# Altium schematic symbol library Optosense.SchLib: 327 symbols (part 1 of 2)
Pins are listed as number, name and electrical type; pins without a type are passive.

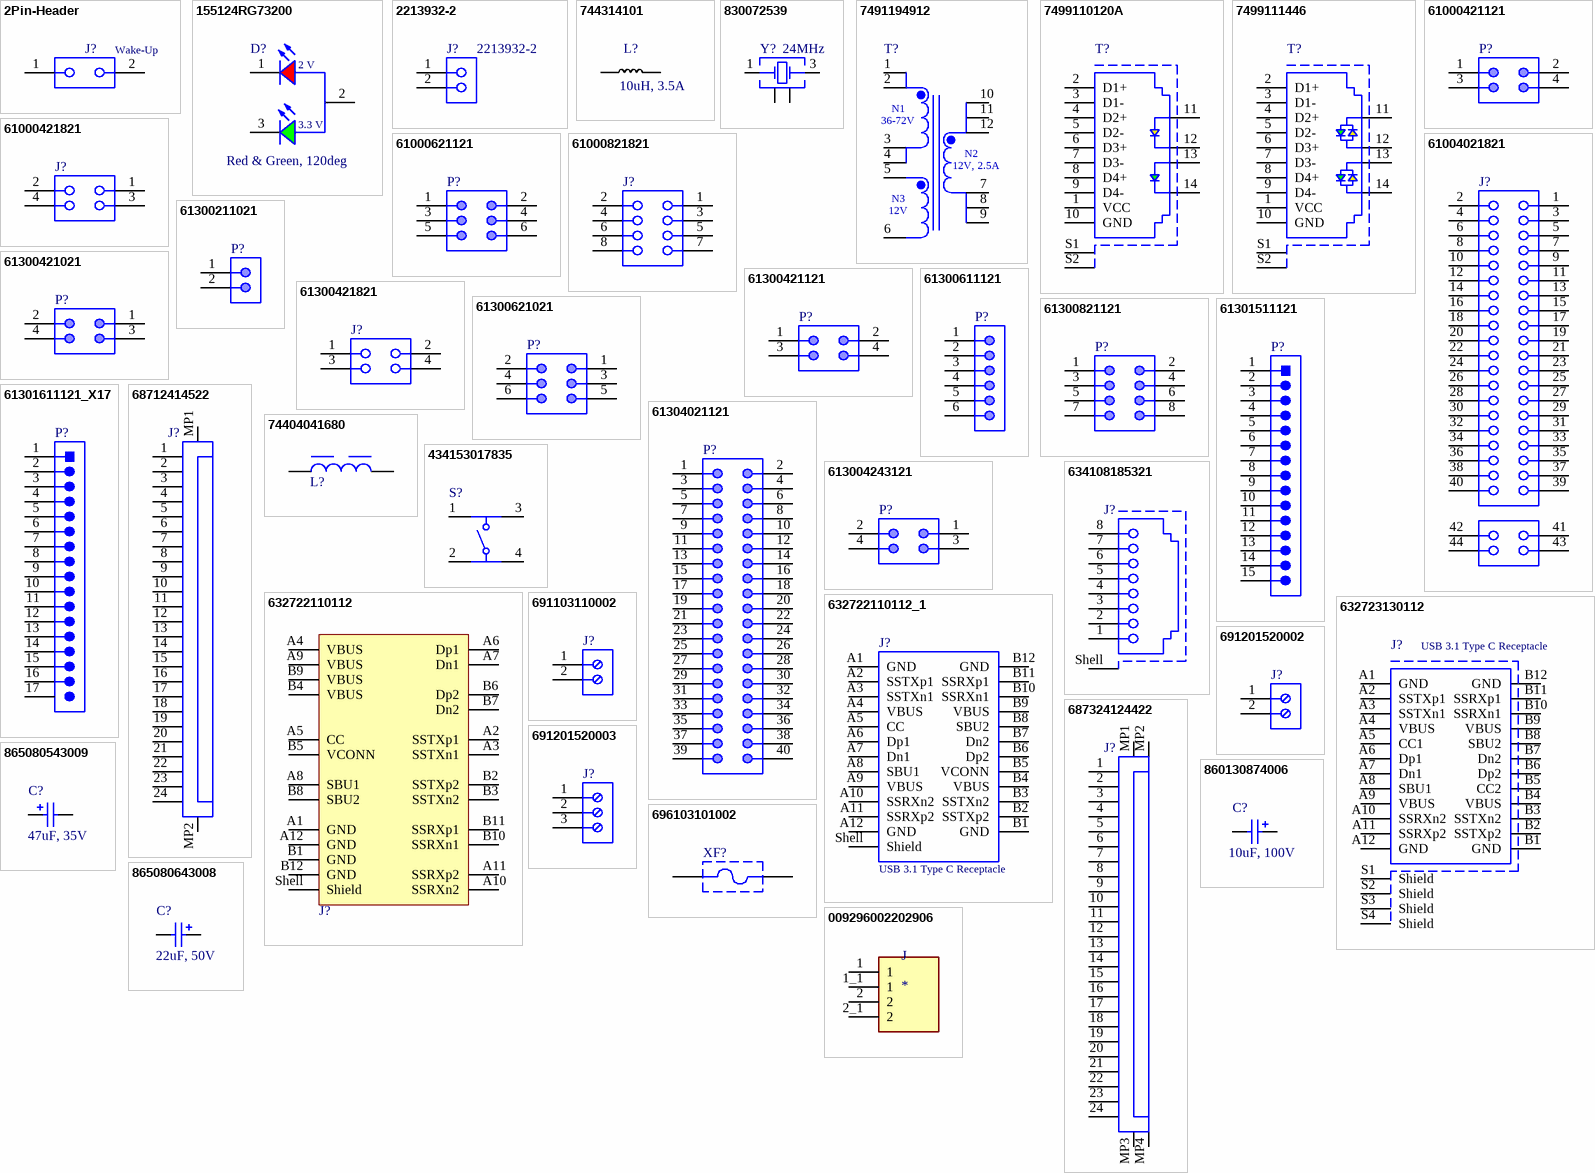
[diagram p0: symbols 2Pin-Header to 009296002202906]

## 2Pin-Header
designator J?, comment Wake-Up
2_Pin-Head_2.54mm
footprint SAMTEC-TSM-102-01-X-SV
pins: 1, 2

## 155124RG73200
designator D?, comment Red & Green, 120deg
WL-SBSW SMT Bi-color Side View Waterclear, size 1204, Red & Green, 120deg; Part Number: 155124RG73200; Luminous Intensity: 160mcd@Green, 60mcd@Red; Dominant Wavelength: 525nm@Green, 624nm@Red; Forward Voltage: 3.3V@Green, 2V@Red; Peak Wavelength: 520nm@Green, 632nm@Red; Chip Technology: AlInGaP + InGaN
footprint WL-SBSW_1204
pins: 1 K, 2 A, 3 K

## 2213932-2
designator J?
SMT TB R/A HEADER, 3.5MM, 2 POS
footprint 2213932-2
pins: 1, 2

## 744314101
designator L?, comment 10uH, 3.5A
WE-HCI SMT Flat Wire High Current Inductor, size 7050, 10uH, 3.5A; Manufacturer Part Number: 744314101; Manufacturer: Wurth Elektronik; DC Resistance: 33mOhm; Material: Superflux; Self Resonant Frequency: 40MHz; Saturation Current: 4A; Rated Inductance: 7.5uH
footprint WE-HCI_7050
pins: 1 (power), 2 (power)

## 830072539
designator Y?, comment 24MHz
WE-XTAL Quartz Crystal, SMT, IQXC-26, 24MHz, +/-15ppm; Manufacturer Part Number: 830072539; Manufacturer: Wurth Elektronik; Load Capacitance: 8pF
footprint WE-XTAL_IQXC-26 (Quartz Crystal, size IQXC-26, body 1.6x1.2mm)
pins: 1 Crystal, 2 GND & Lid, 3 Crystal, 4 GND & Lid

## 7491194912
designator T?
WE-PoE+ Power over Ethernet Plus Transformer, EFD20, 36-72Vin, 12Vout, 30W; Manufacturer Part Number: 7491194912; Manufacturer: Wurth Elektronik; Leakage Inductance: 0.545uH; Insulation Test Voltage: 1500VAC; Inductance: 42uH; Output Current: 2.5A; Output Voltage: 12V; Turns Ratio: 3:1:1; Input Voltage: 36-72V; Saturation Current: 6.6A; Switching Frequency: 250-400kHz
footprint WE-PoE+_EFD20
pins: 1, 2, 3, 4, 5, 6, 7, 8, 9, 10, 11, 12

## 7499110120A
designator T?
WE-RJ45 LAN Transformer, THT, 10/100/1000 Base-T, Port 1x1, Tab Vertical; Manufacturer Part Number: 7499110120A; Manufacturer: Wurth Elektronik; PoE: non-PoE; LED: yellow-green; USB: No
footprint 7499110120A (LAN Transformer, body 21.84x15.95mm)
pins: 1 VCC, 2 D1+, 3 D1-, 4 D2+, 5 D2-, 6 D3+, 7 D3-, 8 D4+, 9 D4-, 10 GND, 11, 12, 13, 14, S1 Shield, S2 Shield

## 7499111446
designator T?
WE-RJ45 LAN Transformer, THT, 10/100/1000 Base-T, Port 1x1, Tab Down; Manufacturer Part Number: 7499111446; Manufacturer: Wurth Elektronik; PoE: non-PoE; LED: green/yellow-green/yellow; USB: No; Shield Tabs: Yes
footprint 7499111446
pins: 1 VCC, 2 D1+, 3 D1-, 4 D2+, 5 D2-, 6 D3+, 7 D3-, 8 D4+, 9 D4-, 10 GND, 11, 12, 13, 14, S1 Shield, S2 Shield

## 61000421121
designator P?
WR-PHD Pin Header, SMT, pitch 2.54mm, Dual Row, Vertical, 4p; Manufacturer Part Number: 61000421121; Manufacturer: Wurth Elektronik; Pin Number: 4; Rated Current: 3A; Working Voltage: 250VAC; Withstanding Voltage: 500VAC; Contact Resistance: 20mOhm
footprint 61000421121 (Pin Header, pitch 2.54 mm, SMD, Vertical, dual row, 4p)
pins: 1, 2, 3, 4

## 61000421821
designator J?
WR-PHD Socket Header, SMT, pitch 2.54mm, Dual Row, Vertical, 4p; Manufacturer Part Number: 61000421821; Manufacturer: Wurth Elektronik; Pin Number: 4; Rated Current: 3A; Working Voltage: 250VAC; Withstanding Voltage: 600VAC; Contact Resistance: 20mOhm
footprint 61000421821
pins: 1, 2, 3, 4

## 61000621121
designator P?
WR-PHD Pin Header, SMT, pitch 2.54mm, Dual Row, Vertical, 6p; Manufacturer Part Number: 61000621121; Manufacturer: Wurth Elektronik; Pin Number: 6; Rated Current: 3A; Working Voltage: 250VAC; Withstanding Voltage: 500VAC; Contact Resistance: 20mOhm
footprint 61000621121
pins: 1, 2, 3, 4, 5, 6

## 61000821821
designator J?
WR-PHD Socket Header, SMT, pitch 2.54mm, Dual Row, Vertical, 8p; Manufacturer Part Number: 61000821821; Manufacturer: Wurth Elektronik; Pin Number: 8; Rated Current: 3A; Working Voltage: 250VAC; Withstanding Voltage: 600VAC; Contact Resistance: 20mOhm
footprint 61000821821
pins: 1, 2, 3, 4, 5, 6, 7, 8

## 61004021821
designator J?
WR-PHD Socket Header, SMT, pitch 2.54mm, Dual Row, Vertical, 40pin; Part Number: 61004021821; Pin Number: 40; Gender: Female; Rated Current: 3A; Working Voltage: 250VAC; Withstanding Voltage: 600VAC; Contact Resistance: 20mOhm
footprint 61004021821
pins: 1, 2, 3, 4, 5, 6, 7, 8, 9, 10, 11, 12, 13, 14, 15, 16, 17, 18, 19, 20, 21, 22, 23, 24, 25, 26, 27, 28, 29, 30, 31, 32, 33, 34, 35, 36, 37, 38, 39, 40, 41, 42, 43, 44

## 61300211021
designator P?
WR-PHD Pin Header, THT, pitch 2.54mm, Single Row, Angled, 2p; Manufacturer Part Number: 61300211021; Manufacturer: Wurth Elektronik; Pin Number: 2; Rated Current: 3A; Working Voltage: 250VAC; Withstanding Voltage: 500VAC; Contact Resistance: 20mOhm
footprint 61300211021
pins: 1, 2

## 61300421021
designator P?
WR-PHD Pin Header, THT, pitch 2.54mm, Dual Row, Angled, 4p; Manufacturer Part Number: 61300421021; Manufacturer: Wurth Elektronik; Pin Number: 4; Rated Current: 3A; Working Voltage: 250VAC; Withstanding Voltage: 500VAC; Contact Resistance: 20mOhm
footprint 61300421021 (Pin Header, pitch 2.54 mm, THT, Angled, dual row, 4p)
pins: 1, 2, 3, 4

## 61300421121
designator P?
WR-PHD Pin Header, THT, pitch 2.54mm, Dual Row, Vertical, 4p; Manufacturer Part Number: 61300421121; Manufacturer: Wurth Elektronik; Pin Number: 4; Rated Current: 3A; Working Voltage: 250VAC; Withstanding Voltage: 500VAC; Contact Resistance: 20mOhm
footprint 61300421121
pins: 1, 2, 3, 4

## 61300421821
designator J?
WR-PHD Socket Header, THT, pitch 2.54mm, Dual Row, Vertical, 4p; Manufacturer Part Number: 61300421821; Manufacturer: Wurth Elektronik; Pin Number: 4; Rated Current: 3A; Working Voltage: 250VAC; Withstanding Voltage: 500VAC; Contact Resistance: 20mOhm
footprint 61300421821 (Socket Header, Pitch 2.54 mm, THT, Vertical, dual row, 4p)
pins: 1, 2, 3, 4

## 61300611121
designator P?
WR-PHD Pin Header, THT, pitch 2.54mm, Single Row, Vertical, 6p; Manufacturer Part Number: 61300611121; Manufacturer: Wurth Elektronik; Pin Number: 6; Rated Current: 3A; Working Voltage: 250VAC; Withstanding Voltage: 500VAC; Contact Resistance: 20mOhm
footprint 61300611121
pins: 1, 2, 3, 4, 5, 6

## 61300621021
designator P?
WR-PHD Pin Header, THT, pitch 2.54mm, Dual Row, Angled, 6p; Manufacturer Part Number: 61300621021; Manufacturer: Wurth Elektronik; Pin Number: 6; Rated Current: 3A; Working Voltage: 250VAC; Withstanding Voltage: 500VAC; Contact Resistance: 20mOhm
footprint 61300621021
pins: 1, 2, 3, 4, 5, 6

## 61300821121
designator P?
WR-PHD Pin Header, THT, pitch 2.54mm, Dual Row, Vertical, 8p; Manufacturer Part Number: 61300821121; Manufacturer: Wurth Elektronik; Pin Number: 8; Rated Current: 3A; Working Voltage: 250VAC; Withstanding Voltage: 500VAC; Contact Resistance: 20mOhm
footprint 61300821121
pins: 1, 2, 3, 4, 5, 6, 7, 8

## 61301511121
designator P?
WR-PHD Pin Header, THT, pitch 2.54mm, Single Row, Vertical, 15p; Manufacturer Part Number: 61301511121; Manufacturer: Wurth Elektronik; Pin Number: 15; Rated Current: 3A; Working Voltage: 250VAC; Withstanding Voltage: 500VAC; Contact Resistance: 20mOhm
footprint 61301511121
pins: 1, 2, 3, 4, 5, 6, 7, 8, 9, 10, 11, 12, 13, 14, 15

## 61301611121_X17
designator P?
WR-PHD Pin Header, THT, pitch 2.54mm, Single Row, Vertical, 16p; Manufacturer Part Number: 61301611121; Manufacturer: Wurth Elektronik; Pin Number: 16; Rated Current: 3A; Working Voltage: 250VAC; Withstanding Voltage: 500VAC; Contact Resistance: 20mOhm
footprint 61301611121_X17 (Pin Header, pitch 2.54 mm, THT, Vertical, single row, 16p)
pins: 1, 2, 3, 4, 5, 6, 7, 8, 9, 10, 11, 12, 13, 14, 15, 16, 17

## 61304021121
designator P?
WR-PHD Pin Header, THT, pitch 2.54mm, Dual Row, Vertical, 40p; Manufacturer Part Number: 61304021121; Manufacturer: Wurth Elektronik; Pin Number: 40; Rated Current: 3A; Working Voltage: 250VAC; Withstanding Voltage: 500VAC; Contact Resistance: 20mOhm
footprint 61304021121
pins: 1, 2, 3, 4, 5, 6, 7, 8, 9, 10, 11, 12, 13, 14, 15, 16, 17, 18, 19, 20, 21, 22, 23, 24, 25, 26, 27, 28, 29, 30, 31, 32, 33, 34, 35, 36, 37, 38, 39, 40

## 68712414522
designator J?
WR-FPC SMT ZIF Horizontal Bottom Contact, pitch 0.5mm, 24p; Part Number: 68712414522; Contact Resistance: 20mOhm; Pin Number: 24; Working Voltage: 50VAC; Rated Current: 0.5A
footprint 68712414522
pins: 1, 2, 3, 4, 5, 6, 7, 8, 9, 10, 11, 12, 13, 14, 15, 16, 17, 18, 19, 20, 21, 22, 23, 24, MP1, MP2

## 74404041680
designator L?, comment 68µH, 0.45A  (value not drawn)
WE-LQS SMT Power Inductor, size 4012, 68µH, 0.45A, 1.495Ω; Manufacturer Part Number: 74404041680; Manufacturer: Wurth Elektronik; Case/Size Code: 4012; Saturation Current: 0.48A; Self Resonant Frequency: 13MHz
footprint WE-LQS_4012 (SMD Power Inductor, 2-Leads, body 4x4mm)
pins: 1, 2

## 434153017835
designator S?
WS-TASV J-Bend SMT Tact Switch, 3.5x2.9x1.7mm, 350gf; Manufacturer Part Number: 434153017835; Manufacturer: Wurth Elektronik; Rated Voltage: 12VDC; Rated Current: 50mA; Washable: No
footprint 434153017835 (Tact Switch, SMD, body 3.5x2.9mm)
pins: 1, 2, 3, 4

## 613004243121
designator P?
WR-PHD Pin Header, THT, pitch 2.54mm, Dual Row, Angled, 4p; Manufacturer Part Number: 61300421021; Manufacturer: Wurth Elektronik; Pin Number: 4; Rated Current: 3A; Working Voltage: 250VAC; Withstanding Voltage: 500VAC; Contact Resistance: 20mOhm
footprint 613004243121
pins: 1, 2, 3, 4

## 632722110112
designator J?  (value not drawn)
WR-USB 3.1 Type C, Receptacle, Vertical, SMT; Manufacturer: Wurth Elektronik; Interface Type: Type C; Number of Ports: 1; Rated Current: 5A; Working Voltage: 20VAC
footprint 632722110112
pins: A1 GND, A2 SSTXp1, A3 SSTXn1, A4 VBUS, A5 CC, A6 Dp1, A7 Dn1, A8 SBU1, A9 VBUS, A10 SSRXn2, A11 SSRXp2, A12 GND, B1 GND, B2 SSTXp2, B3 SSTXn2, B4 VBUS, B5 VCONN, B6 Dp2, B7 Dn2, B8 SBU2, B9 VBUS, B10 SSRXn1, B11 SSRXp1, B12 GND, Shell Shield

## 632722110112_1
designator J?, comment USB 3.1 Type C Receptacle
USB 3.1 Type C, Receptacle, Vertical, SMT; Manufacturer: Wurth Elektronik; Manufacturer Part Number: 632722110112; Rated Current: 5A; Pin Number: 24; Interface Type: Type C; Working Voltage: 20VAC
footprint 632722110112 (USB_Type C 3.1_Vertical_SMT_1,0mm)
pins: A1 GND, A2 SSTXp1, A3 SSTXn1, A4 VBUS, A5 CC, A6 Dp1, A7 Dn1, A8 SBU1, A9 VBUS, A10 SSRXn2, A11 SSRXp2, A12 GND, B1 GND, B2 SSTXp2, B3 SSTXn2, B4 VBUS, B5 VCONN, B6 Dp2, B7 Dn2, B8 SBU2, B9 VBUS, B10 SSRXn1, B11 SSRXp1, B12 GND, Shell Shield

## 632723130112
designator J?, comment USB 3.1 Type C Receptacle
USB 3.1 Type C, Receptacle, Horizontal, THR; Part Number: 632723130112; Rated Current: 5A; Pin Number: 24; Interface Type: Type C; Working Voltage: 20VAC
footprint 632723130112
pins: A1 GND, A2 SSTXp1, A3 SSTXn1, A4 VBUS, A5 CC1, A6 Dp1, A7 Dn1, A8 SBU1, A9 VBUS, A10 SSRXn2, A11 SSRXp2, A12 GND, B1 GND, B2 SSTXp2, B3 SSTXn2, B4 VBUS, B5 CC2, B6 Dp2, B7 Dn2, B8 SBU2, B9 VBUS, B10 SSRXn1, B11 SSRXp1, B12 GND, S1 Shield, S2 Shield, S3 Shield, S4 Shield

## 634108185321
designator J?
WR-MJ Modular Jack SMT Vertical Shielded with Solder Tab 8P8C Top Entry; Manufacturer: Wurth Elektronik; Manufacturer Part Number: 634108185321; Rated Current: 1.5A; Contact Resistance: 30mOhm; Insulation Resistance: 1000MOhm; Working Voltage: 125VAC; Withstanding Voltage: 1000VAC; LED: No; Port Number: 1; Shielded: Yes
footprint 634108185321 (Modular Jack Vertical Shielded SMT  with Solder Tab 8P8C Top Entry)
pins: 1, 2, 3, 4, 5, 6, 7, 8, Shell

## 687324124422
designator J?
WR-FPC SMT ZIF Vertical, pitch 0.5mm, 24p; Part Number: 687324124422; Contact Resistance: 20mOhm; Pin Number: 24; Working Voltage: 50VAC; Rated Current: 0.5A
footprint 687324124422
pins: 1, 2, 3, 4, 5, 6, 7, 8, 9, 10, 11, 12, 13, 14, 15, 16, 17, 18, 19, 20, 21, 22, 23, 24, MP1, MP2, MP3, MP4

## 691103110002
designator J?
WR-TBL Serie 1031 Horizontal Entry Modular, Pressure Clamp, THT, pitch 3.5mm, 2p; Manufacturer Part Number: 691103110002; Manufacturer: Wurth Elektronik; Modularity: Yes; PCB/Cable/Panel: PCB; Pin Number: 2; Rated Current [UL]: 10A; Working Voltage [UL]: 125VAC
footprint 691103110002 (3,50mm - modular - blue - Horizontal wire entry - Pressure clamp - 8,4mm height - 02p)
pins: 1, 2

## 691201520002
designator J?
WR-TBL Serie 2015 45deg Entry Modular, Rising Cage Clamp, pitch 5.08mm, 2p; Part Number: 691201520002; Compliance: ROHS & Reach; Modularity: Yes; PCB/Cable/Panel: PCB; Pin Number: 2; Rated Current [UL]: 16A; Working Voltage [UL]: 300VAC
footprint 691201520002
pins: 1, 2

## 691201520003
designator J?
WR-TBL Serie 2015 45deg Entry Modular, Rising Cage Clamp, pitch 5.08mm, 3p; Part Number: 691201520003; Compliance: ROHS & Reach; Modularity: Yes; PCB/Cable/Panel: PCB; Pin Number: 3; Rated Current [UL]: 16A; Working Voltage [UL]: 300VAC
footprint 691201520003
pins: 1, 2, 3

## 696103101002
designator XF?
WR-FSH Fuseholder SMT Blocks PCB Clip Cover; Manufacturer Part Number: 696103101002; Manufacturer: Wurth Elektronik; Fuse Size: 5x20mm
footprint 696103101002
pins: 1, 2

## 860130874006
designator C?, comment 10uF, 100V
WCAP-ATET Aluminum Electrolytic Capacitor, Radial, THT, D8xH11.5mm, 10uF, 100V; Manufacturer Part Number: 860130874006; Manufacturer: Wurth Elektronik; Dissipation Factor: 7%; Endurance: 1000h; Leakage Current: 10uA; Ripple Current: 60mA; Capacitance Tolerance: +/-20%; Rated Voltage: 100VDC; Technical Reference: ATGE115100M100DSPA7A000
footprint WCAP-ATET_8x11.5
pins: 1 N, 2 P

## 865080543009
designator C?, comment 47uF, 35V
WCAP-ASLI Aluminum Electrolytic Capacitor, V-Chip, SMT, D6.3xH5.5mm, 47uF, 35V; Manufacturer Part Number: 865080543009; Manufacturer: Wurth Elektronik; Technical Reference: ASED055470M035DVCTBB000; Ripple Current: 240mA; Capacitance Tolerance: +/-20%; Leakage Current: 16.45uA; Endurance: 2000h; Dissipation Factor: 14%; Rated Voltage: 35VDC
footprint WCAP-ASLI_D6.3H5.5
pins: 1 P, 2 N

## 865080643008
designator C?, comment 22uF, 50V
WCAP-ASLI Aluminum Electrolytic Capacitor, V-Chip, SMT, D6.3xH5.5mm, 22uF, 50V; Manufacturer Part Number: 865080643008; Manufacturer: Wurth Elektronik; Dissipation Factor: 12%; Endurance: 2000h; Leakage Current: 11uA; Ripple Current: 150mA; Capacitance Tolerance: +/-20%; Rated Voltage: 50VDC; Technical Reference: ASED055220M050DVCTBB000
footprint WCAP-ASLI_6.3x5.5
pins: 1 N, 2 P

## 009296002202906
designator J
2 Position Individual Wires Connector White Poke-In 20-26 AWG Surface Mount, Right Angle; MF: AVX; MP: 009296002202906
footprint AVX_009296002202906
pins: 1, 1_1 1, 2, 2_1 2

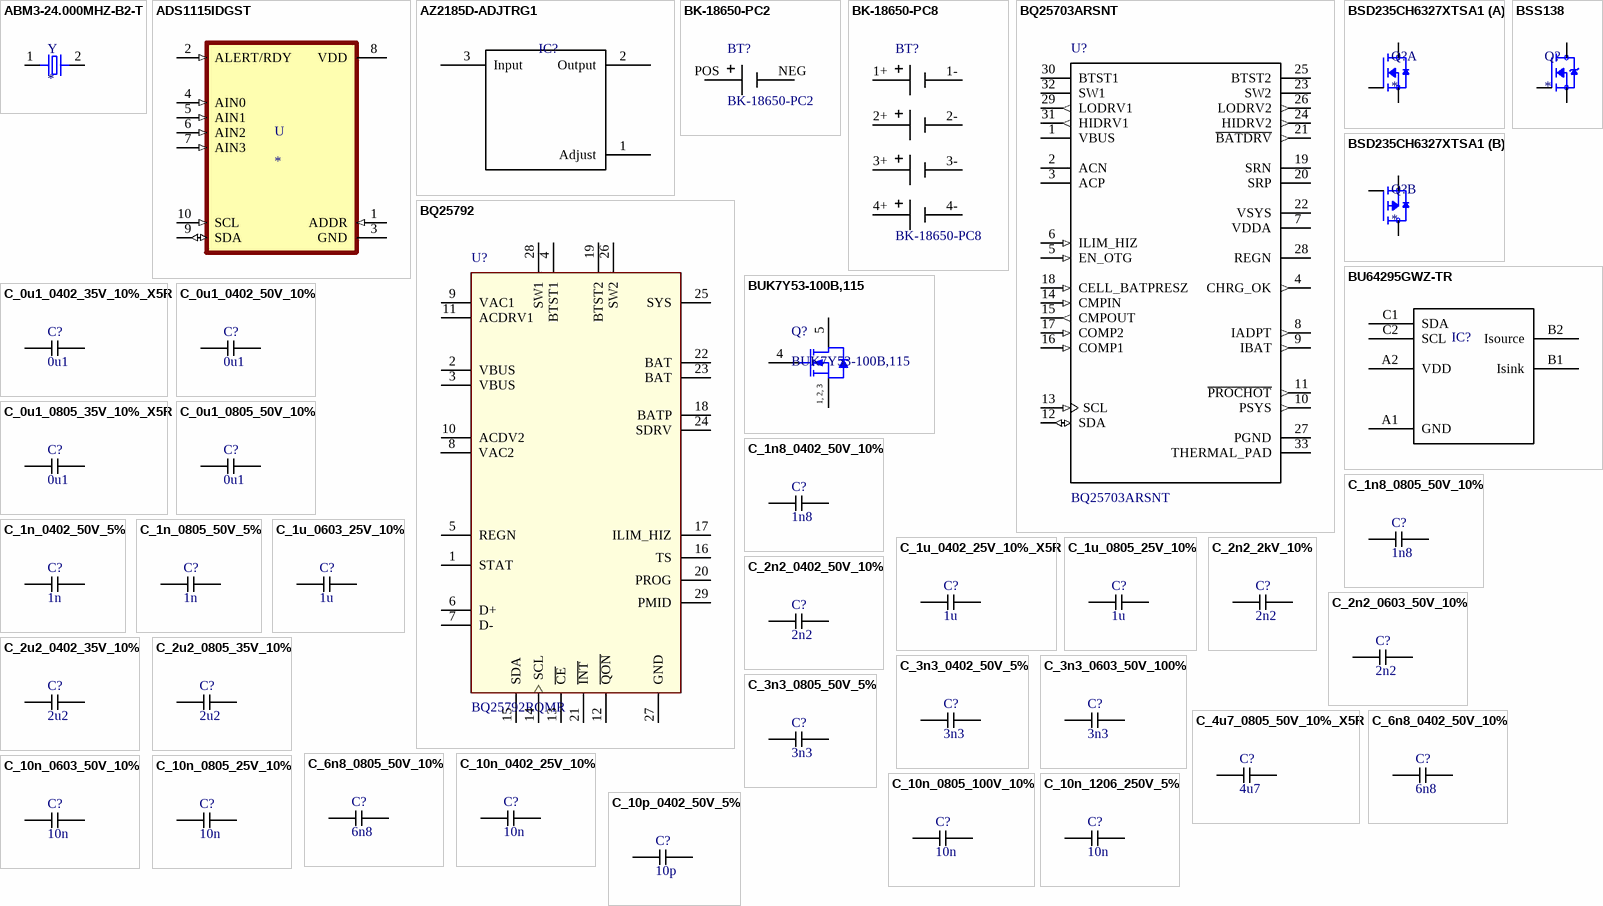
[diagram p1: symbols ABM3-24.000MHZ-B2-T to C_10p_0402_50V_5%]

## ABM3-24.000MHZ-B2-T
designator Y
24MHz Â±20ppm Crystal 18pF 30 Ohms 2-SMD, No Lead; MP: ABM3-24.000MHZ-B2-T; MF: Abracon
footprint XTAL500X320X130N
pins: 1, 2

## ADS1115IDGST
designator U
16-Bit 860SPS 4-Ch Delta-Sigma ADC With PGA, Oscillator, Vref, Comparator, and I2C; MP: ADS1115IDGST; MF: Texas Instruments
footprint SOP50P490X110-10N
pins: 1 ADDR (in), 2 ALERT/RDY (in), 3 GND (power), 4 AIN0 (in), 5 AIN1 (in), 6 AIN2 (in), 7 AIN3 (in), 8 VDD (power), 9 SDA (io), 10 SCL (in)

## AZ2185D-ADJTRG1
designator IC?
footprint DPAK229P990X239-3N
pins: 1 Adjust, 2 Output, 3 Input

## BK-18650-PC2
designator BT?
Battery Holder _Open_ 18650 1 Cell PC Pin; MF: MPD
footprint *BAT_BK-18650-PC2_BK-18650-PC2(Primary)
pins: NEG, POS

## BK-18650-PC8
designator BT?
Battery Holder _Open_ 18650 4 Cell PC Pin; MF: MPD
footprint *BAT_BK-18650-PC8_BK-18650-PC8(Primary)
pins: 1+, 1-, 2+, 2-, 3+, 3-, 4+, 4-

## BQ25703ARSNT
designator U?
Battery Battery Monitor IC Multi-Chemistry 32-WQFN _4x4_; MF: Texas Instruments
footprint *QFN40P400X400X80-33N
pins: 1 VBUS (power), 2 ACN (power), 3 ACP (power), 4 CHRG_OK (out), 5 EN_OTG (in), 6 ILIM_HIZ (in), 7 VDDA (power), 8 IADPT (out), 9 IBAT (out), 10 PSYS (out), 11 ~{PROCHOT} (out), 12 SDA (io), 13 SCL (in), 14 CMPIN (in), 15 CMPOUT (out), 16 COMP1 (in), 17 COMP2 (in), 18 CELL_BATPRESZ (in), 19 SRN (power), 20 SRP (power), 21 ~{BATDRV} (out), 22 VSYS (power), 23 SW2 (power), 24 HIDRV2 (out), 25 BTST2 (power), 26 LODRV2 (out), 27 PGND (power), 28 REGN (power), 29 LODRV1 (out), 30 BTST1 (power), 31 HIDRV1 (out), 32 SW1 (power), 33 THERMAL_PAD (power)

## BQ25792
designator U?, comment BQ25792RQMR
Battery Charger IC, QFN (29) _4x4_; MF: Texas Instruments
footprint Texas_Instruments_RQM0029A_MFG
pins: 1 STAT (power), 2 VBUS (power), 3 VBUS (power), 4 BTST1 (power), 5 REGN (power), 6 D+ (power), 7 D- (power), 8 VAC2 (power), 9 VAC1 (power), 10 ACDV2 (power), 11 ACDRV1 (power), 12 ~{QON} (power), 13 ~{CE} (power), 14 SCL, 15 SDA, 16 TS (power), 17 ILIM_HIZ (power), 18 BATP (power), 19 BTST2 (power), 20 PROG (power), 21 ~{INT} (power), 22 BAT (power), 23 BAT (power), 24 SDRV (power), 25 SYS (power), 26 SW2 (power), 27 GND (power), 28 SW1 (power), 29 PMID (power)

## BSD235CH6327XTSA1
designator Q?
footprint SOT363_INFINEON
part A pins: 1 S, 2 G2, 6 D
part B pins: 3 D, 4 S, 5 G1

## BSS138
designator Q?
N-Channel 50V 220mA (Ta) 360mW (Ta) Surface Mount SOT-23-3; MP: BSS138; MF: ON Semiconductor
footprint SOT95P240X111-3N
pins: 1 G, 2 S, 3 D

## BU64295GWZ-TR
designator IC?
footprint UCSP30L1-6
pins: A1 GND, A2 VDD, B1 Isink, B2 Isource, C1 SDA, C2 SCL

## BUK7Y53-100B,115
designator Q?
N-Channel TrenchMOS Standard Level FET, 100 V, 24.8 A, 5-Pin SOT669, Tape and Reel; Manufacturer: NXP Semiconductors; VGSth [typ] (V): 3; Packing: Tape & Reel; IDM [max] (A): 99; VDS [max] (V): 100; ID [max] (A): 24.8; Channel Type: N; Automotive Qualified: Y; Qr [typ] (nC): 155
footprint NXP-SOT669_M
footprint NXP-SOT669_N
footprint NXP-SOT669_L
pins: 1 S "source", 2 S "source", 3 S "source", 4 G "gate", 5 D "mounting base; connected to drain"

## C_0u1_0402_35V_10%_X5R
designator C?, comment 0u1
GMK105BJ104KV-F
footprint C_0402
pins: 1 (power), 2 (power)

## C_0u1_0402_50V_10%
designator C?, comment 0u1
GRM155R71H104KE14J
footprint C_0402
pins: 1 (power), 2 (power)

## C_0u1_0805_35V_10%_X5R
designator C?, comment 0u1
GMK212BJ104KGHT
footprint C_0805
pins: 1 (power), 2 (power)

## C_0u1_0805_50V_10%
designator C?, comment 0u1
885012207098
footprint C_0805
pins: 1 (power), 2 (power)

## C_1n8_0402_50V_10%
designator C?, comment 1n8
GCM155R71H182JA37D
footprint C_0402
pins: 1 (power), 2 (power)

## C_1n8_0805_50V_10%
designator C?, comment 1n8
CC0805KRX7R9BB182
footprint C_0805
pins: 1 (power), 2 (power)

## C_1n_0402_50V_5%
designator C?, comment 1n
04025C102JAT2A
footprint C_0402
pins: 1 (power), 2 (power)

## C_1n_0805_50V_5%
designator C?, comment 1n
C0805C102J5RAC
footprint C_0805
pins: 1 (power), 2 (power)

## C_1u_0402_25V_10%_X5R
designator C?, comment 1u
04023D105KAT2A
footprint C_0402
pins: 1 (power), 2 (power)

## C_1u_0603_25V_10%
designator C?, comment 1u
TMK107B7105KA-T
footprint C_0603
pins: 1 (power), 2 (power)

## C_1u_0805_25V_10%
designator C?, comment 1u
C0805C105K3RACAUTO
footprint C_0805
pins: 1 (power), 2 (power)

## C_2n2_2kV_10%
designator C?, comment 2n2
CK45-B3DD222KYVNA
footprint C_CK45
pins: 1 (power), 2 (power)

## C_2n2_0402_50V_10%
designator C?, comment 2n2
C0402C222K5RAC
footprint C_0402
pins: 1 (power), 2 (power)

## C_2n2_0603_50V_10%
designator C?, comment 2n2
06035C222KAT4A
footprint C_0603
pins: 1 (power), 2 (power)

## C_2u2_0402_35V_10%
designator C?, comment 2u2
GRM155R6YA225KE11D
footprint C_0402
pins: 1 (power), 2 (power)

## C_2u2_0805_35V_10%
designator C?, comment 2u2
C2012X5R1V225K085AB
footprint C_0805
pins: 1 (power), 2 (power)

## C_3n3_0402_50V_5%
designator C?, comment 3n3
CC0402JRX7R9BB332
footprint C_0402
pins: 1 (power), 2 (power)

## C_3n3_0603_50V_100%
designator C?, comment 3n3
VJ0603Y332KXACW1BC
footprint C_0603
pins: 1 (power), 2 (power)

## C_3n3_0805_50V_5%
designator C?, comment 3n3
CC0805JRX7R9BB332
footprint C_0805
pins: 1 (power), 2 (power)

## C_4u7_0805_50V_10%_X5R
designator C?, comment 4u7
GRM21BR61H475KE51L
footprint C_0805
pins: 1 (power), 2 (power)

## C_6n8_0402_50V_10%
designator C?, comment 6n8
AC0402KRX7R9BB682
footprint C_0402
pins: 1 (power), 2 (power)

## C_6n8_0805_50V_10%
designator C?, comment 6n8
885012207091
footprint C_0805
pins: 1 (power), 2 (power)

## C_10n_0402_25V_10%
designator C?, comment 10n
885012205050
footprint C_0402
pins: 1 (power), 2 (power)

## C_10n_0603_50V_10%
designator C?, comment 10n
C0603C103J5RACTU
footprint C_0603
pins: 1 (power), 2 (power)

## C_10n_0805_25V_10%
designator C?, comment 10n
885012207066
footprint C_0805
pins: 1 (power), 2 (power)

## C_10n_0805_100V_10%
designator C?, comment 10n
C0805C103K1RACTU
footprint C_0805
pins: 1 (power), 2 (power)

## C_10n_1206_250V_5%
designator C?, comment 10n
C1206C103JARACTU
footprint C_1206
pins: 1 (power), 2 (power)

## C_10p_0402_50V_5%
designator C?, comment 10p
885012005055
footprint C_0402
pins: 1 (power), 2 (power)

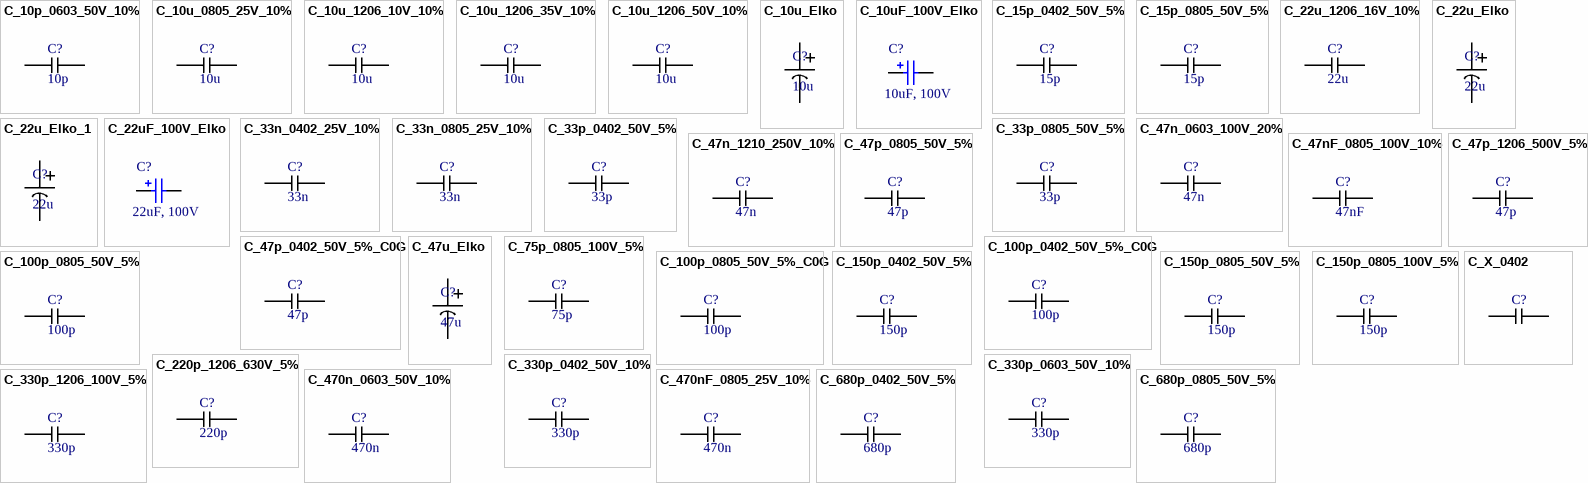
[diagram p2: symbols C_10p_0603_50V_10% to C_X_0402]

## C_10p_0603_50V_10%
designator C?, comment 10p
06035C100K4T4A
footprint C_0603
pins: 1 (power), 2 (power)

## C_10u_0805_25V_10%
designator C?, comment 10u
GRJ21BR61E106KE01K
footprint C_0805
pins: 1 (power), 2 (power)

## C_10u_1206_10V_10%
designator C?, comment 10u
LMK316B7106KL-T
footprint C_1206
pins: 1 (power), 2 (power)

## C_10u_1206_35V_10%
designator C?, comment 10u
GMK316BJ106KL-T
footprint C_1206
pins: 1 (power), 2 (power)

## C_10u_1206_50V_10%
designator C?, comment 10u
UMK316BBJ106KL-T
footprint C_1206
pins: 1 (power), 2 (power)

## C_10u_Elko
designator C?, comment 10u
ECA-2AHG100B
footprint Panasonic_ECA-2AHG220_0
pins: 1 - (power), 2 + (power)

## C_10uF_100V_Elko
designator C?, comment 10uF, 100V
EEE-2AA100P; Manufacturer Part Number: 865080543009; Manufacturer: Wurth Elektronik; Technical Reference: ASED055470M035DVCTBB000; Ripple Current: 240mA; Capacitance Tolerance: +/-20%; Leakage Current: 16.45uA; Endurance: 2000h; Dissipation Factor: 14%; Capacitance: 47uF; Rated Voltage: 35VDC
footprint CAPAE830X1080N
pins: 1 P, 2 N

## C_15p_0402_50V_5%
designator C?, comment 15p
885012005056
footprint C_0402
pins: 1 (power), 2 (power)

## C_15p_0805_50V_5%
designator C?, comment 15p
885012007052
footprint C_0805
pins: 1 (power), 2 (power)

## C_22u_1206_16V_10%
designator C?, comment 22u
EMK316ABJ226KL-T
footprint C_1206
pins: 1 (power), 2 (power)

## C_22u_Elko
designator C?, comment 22u
UKL2A220KPD
footprint C_10x12.5
pins: 1 - (power), 2 + (power)

## C_22u_Elko_1
designator C?, comment 22u
ECA-2AHG220B
footprint Panasonic_ECA-2AHG220_0
pins: 1 - (power), 2 + (power)

## C_22uF_100V_Elko
designator C?, comment 22uF, 100V
EEE-2AA220P; Manufacturer Part Number: 865080543009; Manufacturer: Wurth Elektronik; Technical Reference: ASED055470M035DVCTBB000; Ripple Current: 240mA; Capacitance Tolerance: +/-20%; Leakage Current: 16.45uA; Endurance: 2000h; Dissipation Factor: 14%; Capacitance: 47uF; Rated Voltage: 35VDC
footprint CAPAE830X1080N
pins: 1 P, 2 N

## C_33n_0402_25V_10%
designator C?, comment 33n
885012205053
footprint C_0402
pins: 1 (power), 2 (power)

## C_33n_0805_25V_10%
designator C?, comment 33n
885012207069
footprint C_0805
pins: 1 (power), 2 (power)

## C_33p_0402_50V_5%
designator C?, comment 33p
885012005058
footprint C_0402
pins: 1 (power), 2 (power)

## C_33p_0805_50V_5%
designator C?, comment 33p
C0805C330J5GACTU
footprint C_0805
pins: 1 (power), 2 (power)

## C_47n_0603_100V_20%
designator C?, comment 47n
C0603C473M1RACTU
footprint C_0603
pins: 1 (power), 2 (power)

## C_47n_1210_250V_10%
designator C?, comment 47n
QMK325B7473KN-T
footprint C_1210
pins: 1 (power), 2 (power)

## C_47nF_0805_100V_10%
designator C?, comment 47nF
X7R0805473K100DFCT10000
footprint C_0805
pins: 1 (power), 2 (power)

## C_47p_0402_50V_5%_C0G
designator C?, comment 47p
885012005059
footprint C_0402
pins: 1 (power), 2 (power)

## C_47p_0805_50V_5%
designator C?, comment 47p
C0805C470J5GACTU
footprint C_0805
pins: 1 (power), 2 (power)

## C_47p_1206_500V_5%
designator C?, comment 47p
1206N470J501CT
footprint C_1206
pins: 1 (power), 2 (power)

## C_47u_Elko
designator C?, comment 47u
860020572006
footprint C_5X11
pins: 1 - (power), 2 + (power)

## C_75p_0805_100V_5%
designator C?, comment 75p
08051A750JAT2A
footprint C_0805
pins: 1 (power), 2 (power)

## C_100p_0402_50V_5%_C0G
designator C?, comment 100p
CC0402JRNPO9BN101
footprint C_0402
pins: 1 (power), 2 (power)

## C_100p_0805_50V_5%
designator C?, comment 100p
08055C101JAT2A
footprint C_0805
pins: 1 (power), 2 (power)

## C_100p_0805_50V_5%_C0G
designator C?, comment 100p
CC0805JRNPO9BN101
footprint C_0805
pins: 1 (power), 2 (power)

## C_150p_0402_50V_5%
designator C?, comment 150p
C0402C151J5GACAUTO
footprint C_0402
pins: 1 (power), 2 (power)

## C_150p_0805_50V_5%
designator C?, comment 150p
885012007058
footprint C_0805
pins: 1 (power), 2 (power)

## C_150p_0805_100V_5%
designator C?, comment 150p
885012007083
footprint C_0805
pins: 1 (power), 2 (power)

## C_220p_1206_630V_5%
designator C?, comment 220p
1206N221J631CT
footprint C_1206
pins: 1 (power), 2 (power)

## C_330p_0402_50V_10%
designator C?, comment 330p
CC0402KRX7R9BB331
footprint C_0402
pins: 1 (power), 2 (power)

## C_330p_0603_50V_10%
designator C?, comment 330p
C0603C331K5RAC
footprint C_0603
pins: 1 (power), 2 (power)

## C_330p_1206_100V_5%
designator C?, comment 330p
885012008070
footprint C_1206
pins: 1 (power), 2 (power)

## C_470n_0603_50V_10%
designator C?, comment 470n
UMK107B7474KA-TR
footprint C_0603
pins: 1 (power), 2 (power)

## C_470nF_0805_25V_10%
designator C?, comment 470n
885012207076
footprint C_0805
pins: 1 (power), 2 (power)

## C_680p_0402_50V_5%
designator C?, comment 680p
GRM1555C1H681JA01D
footprint C_0402
pins: 1 (power), 2 (power)

## C_680p_0805_50V_5%
designator C?, comment 680p
885012007062
footprint C_0805
pins: 1 (power), 2 (power)

## C_X_0402
designator C?
footprint C_0402
pins: 1 (power), 2 (power)

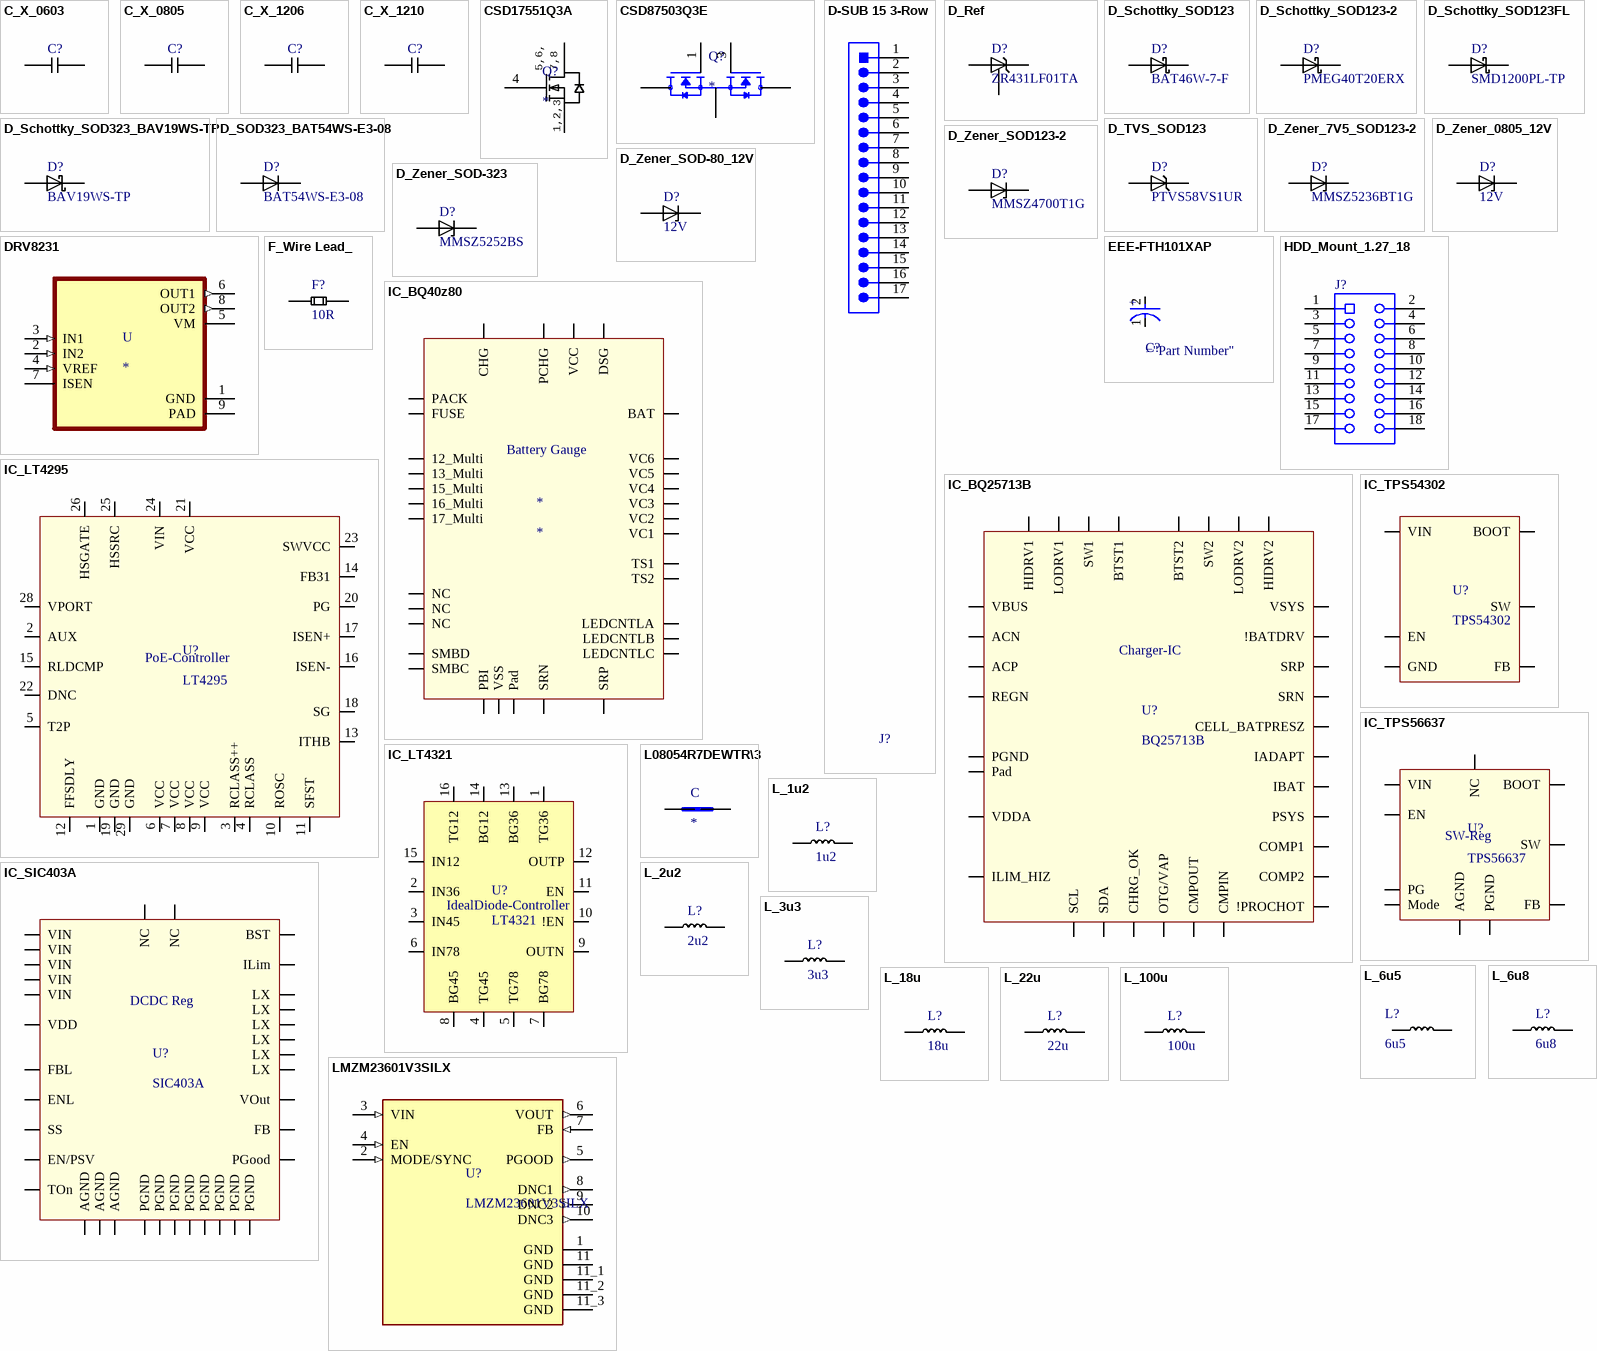
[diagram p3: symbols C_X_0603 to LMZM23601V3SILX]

## C_X_0603
designator C?
footprint C_0603
pins: 1 (power), 2 (power)

## C_X_0805
designator C?
footprint C_0805
pins: 1 (power), 2 (power)

## C_X_1206
designator C?
footprint C_1206
pins: 1 (power), 2 (power)

## C_X_1210
designator C?
footprint C_1210
pins: 1 (power), 2 (power)

## CSD17551Q3A
designator Q?
No Description Available; PartNumber: CSD18543Q3A; Manufacturer: Texas Instruments; Value: 60V; Type: DEV; VALUE_2: Value
footprint DNH0008A
pins: 1 S, 2 S, 3 S, 4 G, 5 D, 6 D, 7 D, 8 D, 9 D

## CSD87503Q3E
designator Q?
30V, N ch NexFET MOSFET, dual common source SON3x3, 21.9mOhm 8-VSON -55 to 150; MF: Texas Instruments; MP: CSD87503Q3E
footprint CSD87503Q3E
pins: 1 G1, 2 S, 3 G2, 4 S, 9 D1, 9.1 D1, 9.2 D1, 10 D2, 10.1 D2, 10.2 D2

## D-SUB 15 3-Row
designator J?  (value not drawn)
footprint TE_1-1734530-3_0
pins: 1, 2, 3, 4, 5, 6, 7, 8, 9, 10, 11, 12, 13, 14, 15, 16, 17

## D_Ref
designator D?, comment ZR431LF01TA
footprint IC_SOT-23-3
pins: 1 (power), 2 (power), 3 (power)

## D_Schottky_SOD123
designator D?, comment BAT46W-7-F
footprint D_SOD123
pins: A (power), K (power)

## D_Schottky_SOD123-2
designator D?, comment PMEG40T20ERX
footprint D_SOD123-2
pins: A (power), K (power)

## D_Schottky_SOD123FL
designator D?, comment SMD1200PL-TP
footprint D_SOD123FL
pins: A (power), K (power)

## D_Schottky_SOD323_BAV19WS-TP
designator D?, comment BAV19WS-TP
footprint D_SOD323
pins: A (power), K (power)

## D_SOD323_BAT54WS-E3-08
designator D?, comment BAT54WS-E3-08
footprint D_SOD323
pins: A (power), K (power)

## D_TVS_SOD123
designator D?, comment PTVS58VS1UR
TVS_58V_SOD123_PTVS58VS1UR
footprint D_SOD123
pins: A (power), K (power)

## D_Zener_7V5_SOD123-2
designator D?, comment MMSZ5236BT1G
7V5_MMSZ5236BT1G
footprint D_SOD123-2
pins: 1 (power), 2 (power)

## D_Zener_0805_12V
designator D?, comment 12V
12V BZY55B12RBG
footprint RESC0805X60N
pins: 1 (power), 2 (power)

## D_Zener_SOD123-2
designator D?, comment MMSZ4700T1G
13V_MMSZ4700T1G
footprint D_SOD123-2
pins: A (power), K (power)

## D_Zener_SOD-80_12V
designator D?, comment 12V
12V BZT55C12-GS08
footprint MELF_SOD-80
pins: 1 (power), 2 (power)

## D_Zener_SOD-323
designator D?, comment MMSZ5252BS
24V_MMSZ5252BS
footprint SOD323
pins: A (power), K (power)

## DRV8231
designator U
45-V, 3.6-A H-bridge motor driver with integrated current sensing 8-SO PowerPAD -40 to 125; MP: DRV8871DDA; MF: Texas Instruments
footprint WSON-8 (SON, 8-Leads, Body 2,00x2,00mm, Pitch 0,50mm, Thermal Pad 1,60x0,68mm, IPC Medium Density)
pins: 1 GND (power), 2 IN2 (in), 3 IN1 (in), 4 VREF (in), 5 VM (power), 6 OUT1 (out), 7 ISEN (power), 8 OUT2 (out), 9 PAD (power)

## EEE-FTH101XAP
designator C?  (value not drawn)
pins: 1 C, 2 A

## F_Wire Lead_
designator F?, comment 10R
NFR2500001009JA500
footprint RT_Via (NTCALUG01A103F161L)
pins: 1 (power), 2 (power)

## HDD_Mount_1.27_18
designator J?
WR-PHD Socket Header, SMT, pitch 1.27mm, Dual Row, Vertical, 26p; Manufacturer Part Number: 623326235321; Manufacturer: Wurth Elektronik; Pin Number: 26; Rated Current: 1A; Working Voltage: 250VAC; Withstanding Voltage: 500VAC; Contact Resistance: 20mOhm
footprint 623326235321
footprint HDD_Mount_1.27_18 (Socket Header, Pitch 1.27 mm, SMT, Vertical, dual row, 26p)
pins: 1, 2, 3, 4, 5, 6, 7, 8, 9, 10, 11, 12, 13, 14, 15, 16, 17, 18

## IC_BQ40z80
designator *
footprint VQFN32
pins: 1 VC5 (power), 2 VC4 (power), 3 VC3 (power), 4 VC2 (power), 5 VC1 (power), 6 SRN (power), 7 NC (power), 8 SRP (power), 9 VSS (power), 10 TS1 (power), 11 TS2 (power), 12 12_Multi (power), 13 13_Multi (power), 14 NC (power), 15 15_Multi (power), 16 16_Multi (power), 17 17_Multi (power), 18 SMBD (power), 19 SMBC (power), 20 LEDCNTLA (power), 21 LEDCNTLB (power), 22 LEDCNTLC (power), 23 FUSE (power), 24 VCC (power), 25 PACK (power), 26 DSG (power), 27 NC (power), 28 PCHG (power), 29 CHG (power), 30 BAT (power), 31 PBI (power), 32 VC6 (power), 33 Pad (power)

## IC_BQ25713B
designator U?, comment BQ25713B
footprint WQFN_32
pins: 1 VBUS (power), 2 ACN (power), 3 ACP (power), 4 CHRG_OK (power), 5 OTG/VAP (power), 6 ILIM_HIZ (power), 7 VDDA (power), 8 IADAPT (power), 9 IBAT (power), 10 PSYS (power), 11 !PROCHOT (power), 12 SDA (power), 13 SCL (power), 14 CMPIN (power), 15 CMPOUT (power), 16 COMP1 (power), 17 COMP2 (power), 18 CELL_BATPRESZ (power), 19 SRN (power), 20 SRP (power), 21 !BATDRV (power), 22 VSYS (power), 23 SW2 (power), 24 HIDRV2 (power), 25 BTST2 (power), 26 LODRV2 (power), 27 PGND (power), 28 REGN (power), 29 LODRV1 (power), 30 BTST1 (power), 31 HIDRV1 (power), 32 SW1 (power), Pad (power)

## IC_LT4295
designator U?, comment LT4295
footprint IC_QNF_28_PLASTIC
pins: 1 GND (power), 2 AUX (power), 3 RCLASS++ (power), 4 RCLASS (power), 5 T2P (power), 6 VCC (power), 7 VCC (power), 8 VCC (power), 9 VCC (power), 10 ROSC (power), 11 SFST (power), 12 FFSDLY (power), 13 ITHB (power), 14 FB31 (power), 15 RLDCMP (power), 16 ISEN- (power), 17 ISEN+ (power), 18 SG (power), 19 GND (power), 20 PG (power), 21 VCC (power), 22 DNC (power), 23 SWVCC (power), 24 VIN (power), 25 HSSRC (power), 26 HSGATE (power), 28 VPORT (power), 29 GND (power)

## IC_LT4321
designator U?, comment LT4321
LT4321IUF
footprint IC_QFN_16_Plastic
pins: 1 TG36 (power), 2 IN36 (power), 3 IN45 (power), 4 TG45 (power), 5 TG78 (power), 6 IN78 (power), 7 BG78 (power), 8 BG45 (power), 9 OUTN (power), 10 !EN (power), 11 EN (power), 12 OUTP (power), 13 BG36 (power), 14 BG12 (power), 15 IN12 (power), 16 TG12 (power)

## IC_SIC403A
designator U?, comment SIC403A
footprint MLP55-32L
pins: 1 FB (power), 2 VOut (power), 3 VDD (power), 4 AGND (power), 5 FBL (power), 6 VIN (power), 7 SS (power), 8 BST (power), 9 VIN (power), 10 VIN (power), 11 VIN (power), 12 NC (power), 13 LX (power), 14 NC (power), 15 PGND (power), 16 PGND (power), 17 PGND (power), 18 PGND (power), 19 PGND (power), 20 PGND (power), 21 PGND (power), 22 PGND (power), 23 LX (power), 24 LX (power), 25 LX (power), 26 PGood (power), 27 ILim (power), 28 LX (power), 29 EN/PSV (power), 30 AGND (power), 31 TOn (power), 32 ENL (power), Pad1 AGND (power), Pad2 VIN (power), Pad3 LX (power)

## IC_TPS54302
designator U?, comment TPS54302
footprint SOT-23-THIN
pins: 1 GND (power), 2 SW (power), 3 VIN (power), 4 FB (power), 5 EN (power), 6 BOOT (power)

## IC_TPS56637
designator U?, comment TPS56637
footprint VQFN-HR
pins: 1 EN (power), 2 FB (power), 3 AGND (power), 4 PG (power), 5 NC (power), 6 SW (power), 7 BOOT (power), 8 VIN (power), 9 PGND (power), 10 Mode (power)

## L08054R7DEWTR\3
designator C
4.7nH Unshielded Thin Film Inductor 750mA 100mOhm Max 0805 (2012 Metric); MP: L08054R7DEWTR; MF: AVX
footprint CAPC2012X140N
pins: 1, 2

## L_1u2
designator L?, comment 1u2
XAL5030-122MEC
footprint L_XAL5030
pins: 1 (power), 2 (power)

## L_2u2
designator L?, comment 2u2
ASPI-0630HI-2R2M-T15
footprint L_ASPI-0630HI-2R2M-T15 (ASPI-0630HI-2R2M-T15)
pins: 1 (power), 2 (power)

## L_3u3
designator L?, comment 3u3
ASPI-0630HI-3R3M-T15
footprint L_ASPI-0630HI-2R2M-T15 (ASPI-0630HI-2R2M-T15)
pins: 1 (power), 2 (power)

## L_6u5
designator L?, comment 6u5
744314650
footprint WE-HCI_7050 (SMT Flat Wire High Current Inductor, body 6.9x6.9mm)
pins: 1 (power), 2 (power)

## L_6u8
designator L?, comment 6u8
SRN5020TA-6R8M
footprint SRN5020TA
pins: 1 (power), 2 (power)

## L_18u
designator L?, comment 18u
SRN1060-180M
footprint SRN1060
pins: 1 (power), 2 (power)

## L_22u
designator L?, comment 22u
XAL6060-223MEC
footprint L_PA4342.223NLT
pins: 1 (power), 2 (power)

## L_100u
designator L?, comment 100u
NRS6028T101MMGJ
footprint L_6028 (NRS6028T101MMGJ)
pins: 1 (power), 2 (power)

## LMZM23601V3SILX
designator U?
4V to 36V, 1A Step-Down Converter Module With Integrated Inductor in 3x3.8x1.6mm Package 10-uSiP -40 to 125; MF: Texas Instruments
footprint CONV_LMZM23601V3XXXX
pins: 1 GND (power), 2 MODE/SYNC (in), 3 VIN (in), 4 EN (in), 5 PGOOD (out), 6 VOUT (out), 7 FB (in), 8 DNC1 (out), 9 DNC2 (out), 10 DNC3 (out), 11 GND (power), 11_1 GND (power), 11_2 GND (power), 11_3 GND (power)

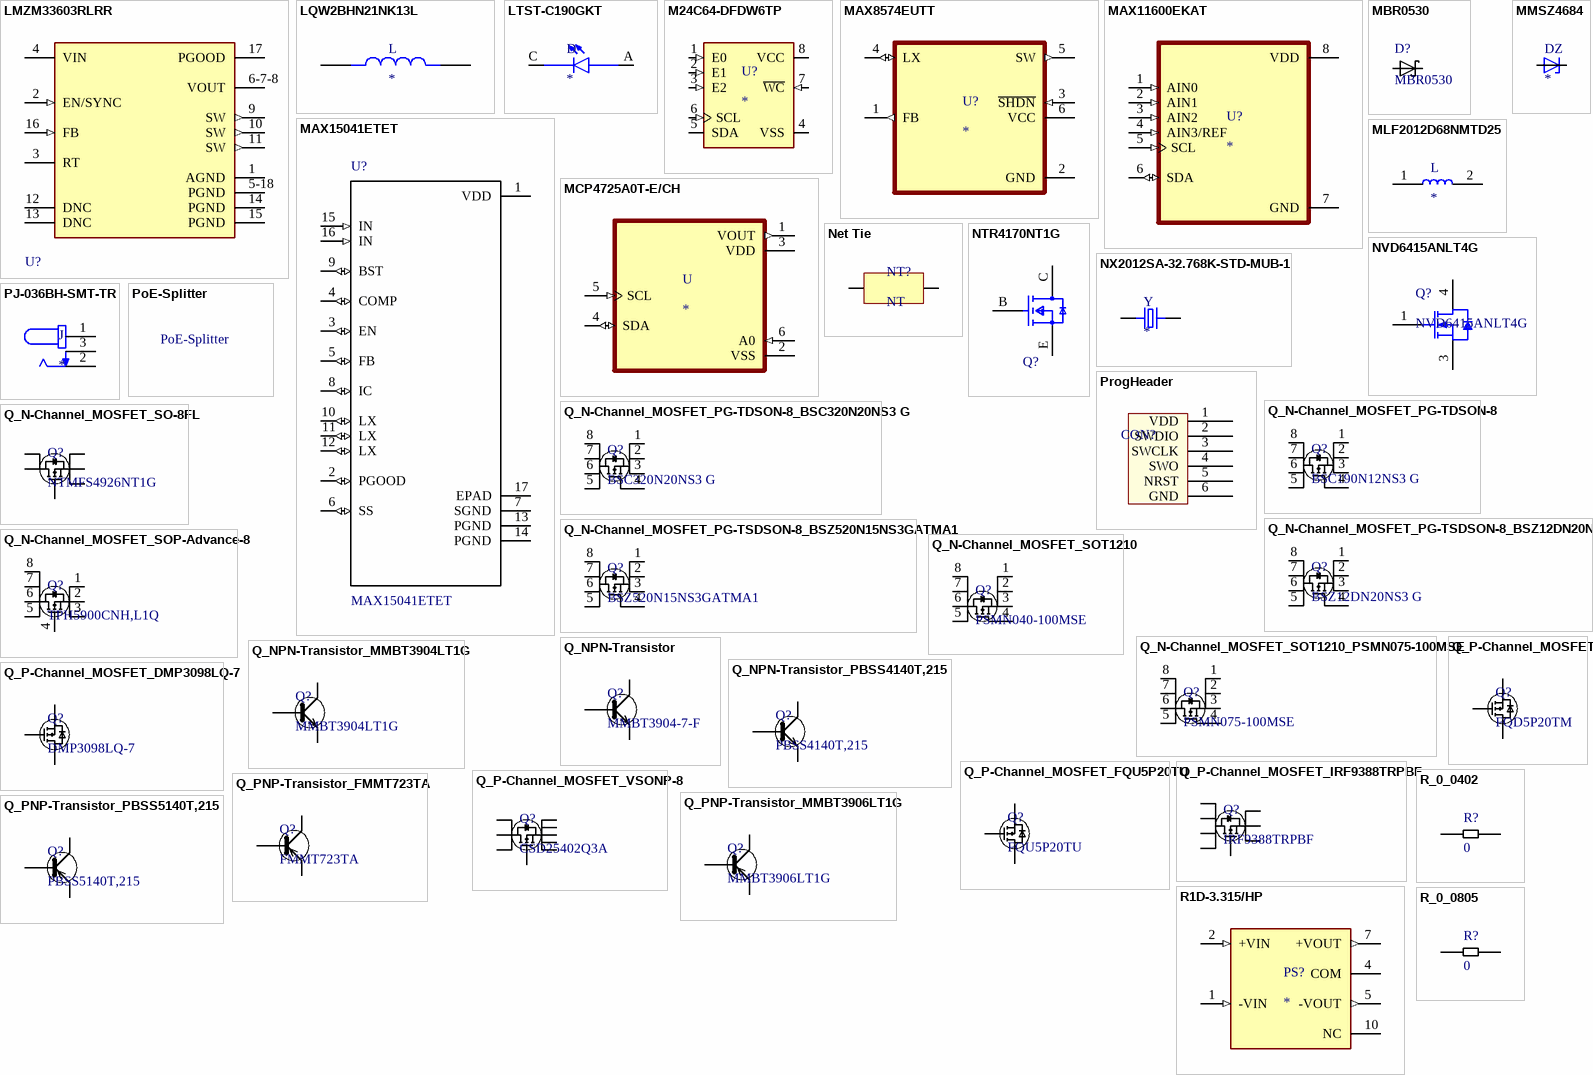
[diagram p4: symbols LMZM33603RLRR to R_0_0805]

## LMZM33603RLRR
designator U?  (value not drawn)
footprint Texas_Instruments_RLR0018A_MFG
pins: 1 AGND (power), 2 EN/SYNC (in), 3 RT, 4 VIN (power), 5-18 PGND (power), 6-7-8 VOUT (power), 9 SW (out), 10 SW (out), 11 SW (out), 12 DNC, 13 DNC, 14 PGND (power), 15 PGND (power), 16 FB (in), 17 PGOOD (oc)

## LQW2BHN21NK13L
designator L
Inductor with Inductance: 21nH Tol. +/-10%, Package: 0805 (2015); MF: Murata; MP: LQW2BHN21NK13L
footprint IND_LQW2BHN21NK13L
pins: 1, 2

## LTST-C190GKT
designator D
Green 569nm LED Indication - Discrete 2.1V 0603 (1608 Metric); MF: Lite-On Inc.; MP: LTST-C190GKT
footprint LEDM1608X80
pins: A, C

## M24C64-DFDW6TP
designator U?
M24C02-F Series 2 Kb (256 x 8) 5.5 V Serial IÂ²C bus EEPROMs - TSSOP-8; MP: M24C64-DFDW6TP
footprint SOP65P640X120-8N
pins: 1 E0 (in), 2 E1 (in), 3 E2 (in), 4 VSS (power), 5 SDA (io), 6 SCL (in), 7 ~{WC} (in), 8 VCC (power)

## MAX8574EUTT
designator U?
- Converter, LCD Voltage Regulator IC 1 Output SOT-23-6; MF: Maxim Integrated; MP: MAX8574EUT+
footprint SOT95P280X145-6N
pins: 1 FB (out), 2 GND (power), 3 ~{SHDN} (in), 4 LX (io), 5 SW (out), 6 VCC (power)

## MAX11600EKAT
designator U?
8 Bit Analog to Digital Converter 2, 4 Input 1 SAR SOT-23-8; MP: MAX11600EKA+T; MF: Maxim Integrated
footprint SOT65P280X145-8N
pins: 1 AIN0 (in), 2 AIN1 (in), 3 AIN2 (in), 4 AIN3/REF (in), 5 SCL (in), 6 SDA (io), 7 GND (power), 8 VDD (power)

## MAX15041ETET
designator U?
Low-Cost, 3A, 4.5V to 28V Input, 350kHz, PWM Step-Down DC-DC Regulatorwith Inter; MF: Maxim Integrated; MP: MAX15041ETE+
footprint *QFN50P300X300X80-17N
pins: 1 VDD (power), 2 PGOOD (io), 3 EN (io), 4 COMP (io), 5 FB (io), 6 SS (io), 7 SGND (power), 8 IC (io), 9 BST (io), 10 LX (io), 11 LX (io), 12 LX (io), 13 PGND (power), 14 PGND (power), 15 IN (in), 16 IN (in), 17 EPAD (power)

## MBR0530
designator D?
footprint *SOD123_MBR0530(Primary)
pins: A, C

## MCP4725A0T-E/CH
designator U
12 Bit Digital to Analog Converter 1 SOT-23-6; MF: Microchip; MP: MCP4725A0T-E/CH
footprint SOT95P270X145-6N
pins: 1 VOUT (out), 2 VSS (power), 3 VDD (power), 4 SDA (io), 5 SCL (in), 6 A0 (in)

## MLF2012D68NMTD25
designator L
Fixed Ind 68nh 300ma 150 Mohm; MF: TDK; MP: MLF2012D68NMTD25
footprint INDC2012X87N
pins: 1, 2

## MMSZ4684
designator DZ
Zener Diode 3.3V 500mW Â±5% Surface Mount SOD-123; MF: ON Semiconductor; MP: MMSZ4684
footprint SOD-123
pins: A, C

## Net Tie
designator NT?, comment NT  (net tie, no BOM)
footprint Net Tie
pins: 1 (power), 2 (power)

## NTR4170NT1G
designator Q?  (value not drawn)
footprint SOT-23-3
pins: B Gate, C 3, E Source

## NVD6415ANLT4G
designator Q?
N-Channel Power MOSFET, 100 V, 23 A, 56 mOhm, Logic Level, 3-Pin DPAK, Pb-Free, Tape and Reel; Manufacturer: On Semiconductor; PD Max (W): 83; VGS(th) Max (V): 2; Crss Typ (pF): 70; Channel Polarity: N Channel; Coss Typ (pF): 156; ID Max (A): 23; Configuration: Single; Qrr Typ (nC): 152; Ciss Typ (pF): 1024; VGS Max (V): 20
footprint ONSC-DPAK-3-369AA-01_V
pins: 1 G, 3 S, 4 D

## NX2012SA-32.768K-STD-MUB-1
designator Y
32.768kHz Â±20ppm Crystal 12.5pF 80 kOhms 2-SMD, No Lead; MP: NX2012SA-32.768K-STD-MUB-1; MF: NDK America,
footprint XTAL_NX2012SA-32.768K-STD-MUB-1
pins: 1, 2

## PJ-036BH-SMT-TR
designator J
2.5 x 6.3 mm, 5.0 A, Horizontal, Surface Mount _SMT_, Dc Power Jack Connector; MP: PJ-036BH-SMT-TR; MF: CUI Devices
footprint CUI_PJ-036BH-SMT-TR
pins: 1, 2, 3

## PoE-Splitter
designator ?
footprint Splitter

## ProgHeader
designator CON?
footprint 1.27_6x
footprint 1.27_6x - NO3D
pins: 1 VDD, 2 SWDIO, 3 SWCLK, 4 SWO, 5 NRST, 6 GND

## Q_N-Channel_MOSFET_PG-TDSON-8
designator Q?, comment BSC190N12NS3 G
N-Channel MOSFET
footprint PG-TDSON-8
pins: 1 S (power), 2 S (power), 3 S (power), 4 9 (power), 5 (power), 6 (power), 7 (power), 8 (power)

## Q_N-Channel_MOSFET_PG-TDSON-8_BSC320N20NS3 G
designator Q?, comment BSC320N20NS3 G
footprint PG-TDSON-8
pins: 1 S (power), 2 S (power), 3 S (power), 4 9 (power), 5 (power), 6 (power), 7 (power), 8 (power)

## Q_N-Channel_MOSFET_PG-TSDSON-8_BSZ12DN20NS3 G
designator Q?, comment BSZ12DN20NS3 G
N-Channel MOSFET
footprint PG-TSDSON-8
pins: 1 S (power), 2 S (power), 3 S (power), 4 9 (power), 5 (power), 6 (power), 7 (power), 8 (power)

## Q_N-Channel_MOSFET_PG-TSDSON-8_BSZ520N15NS3GATMA1
designator Q?, comment BSZ520N15NS3GATMA1
N-Channel MOSFET
footprint PG-TSDSON-8
pins: 1 S (power), 2 S (power), 3 S (power), 4 9 (power), 5 (power), 6 (power), 7 (power), 8 (power)

## Q_N-Channel_MOSFET_SO-8FL
designator Q?, comment NTMFS4926NT1G
footprint SO-8FL (NTMFS4926NT1G)
pins: 1 S (power), 2 S (power), 3 S (power), 4 G (power), 5 D (power), 6 D (power)

## Q_N-Channel_MOSFET_SOP-Advance-8
designator Q?, comment TPH5900CNH,L1Q
N-Channel MOSFET
footprint SOP-Advance-8
pins: 1 S (power), 2 S (power), 3 S (power), 4 9 (power), 5 (power), 6 (power), 7 (power), 8 (power)

## Q_N-Channel_MOSFET_SOT1210
designator Q?, comment PSMN040-100MSE
N-Channel MOSFET_PSMN040-100MSE
footprint SOT1210
pins: 1 S (power), 2 S (power), 3 S (power), 4 9 (power), 5 (power), 6 (power), 7 (power), 8 (power)

## Q_N-Channel_MOSFET_SOT1210_PSMN075-100MSE
designator Q?, comment PSMN075-100MSE
N-Channel MOSFET_PSMN075-100MSE
footprint SOT1210
pins: 1 S (power), 2 S (power), 3 S (power), 4 9 (power), 5 (power), 6 (power), 7 (power), 8 (power)

## Q_NPN-Transistor
designator Q?, comment MMBT3904-7-F
NPN
footprint SOT-23-3
pins: B (power), C (power), E (power)

## Q_NPN-Transistor_MMBT3904LT1G
designator Q?, comment MMBT3904LT1G
footprint SOT-23-3
pins: B (power), C (power), E (power)

## Q_NPN-Transistor_PBSS4140T,215
designator Q?, comment PBSS4140T,215
footprint SOT-23-3
pins: B (power), C (power), E (power)

## Q_P-Channel_MOSFET
designator Q?, comment FQD5P20TM
P-Channel MOSFET
footprint Q_TO-252-3
pins: 1 G (power), 3 S (power), 4 D (power)

## Q_P-Channel_MOSFET_DMP3098LQ-7
designator Q?, comment DMP3098LQ-7
footprint SOT-23-3
pins: B G (power), C D (power), E S (power)

## Q_P-Channel_MOSFET_FQU5P20TU
designator Q?, comment FQU5P20TU
P-Channel MOSFET_FQU5P20TU
footprint TO-251-3L
pins: 1 G (power), 2 D (power), 3 S (power)

## Q_P-Channel_MOSFET_IRF9388TRPBF
designator Q?, comment IRF9388TRPBF
P-Channel MOSFET_IRF9388TRPBF
footprint SO-8
pins: 1 S (power), 2 S (power), 3 S (power), 4 9 (power), 5 (power), 6 (power), 7 (power), 8 (power)

## Q_P-Channel_MOSFET_VSONP-8
designator Q?, comment CSD25402Q3A
P-Channel MOSFET_CSD25402Q3A
footprint VSONP-8 (CSD25402Q3A)
pins: 1 D (power), 2 D (power), 3 D (power), 4 G (power), 5 S (power), 6 S (power), 7 S (power), 8 S (power), 9 S (power)

## Q_PNP-Transistor_FMMT723TA
designator Q?, comment FMMT723TA
PNP_FMMT723TA
footprint SOT-23-3
pins: B (power), C (power), E (power)

## Q_PNP-Transistor_MMBT3906LT1G
designator Q?, comment MMBT3906LT1G
PNP_MMBT3906LT1G
footprint SOT-23-3
pins: B (power), C (power), E (power)

## Q_PNP-Transistor_PBSS5140T,215
designator Q?, comment PBSS5140T,215
PNP_PBSS5140T,215
footprint SOT-23-3
pins: B (power), C (power), E (power)

## R1D-3.315/HP
designator PS?
1 Watt SMD Single & Dual Output; MP: R1D-3.315/HP
footprint CONV_R1D-3.315/HP
pins: 1 -VIN (in), 2 +VIN (in), 4 COM (power), 5 -VOUT (out), 7 +VOUT (out), 10 NC

## R_0_0402
designator R?, comment 0
CRCW04020000Z0EDC
footprint R_0402
pins: 1 (power), 2 (power)

## R_0_0805
designator R?, comment 0
CRCW08050000Z0EAC
footprint R_0805
pins: 1 (power), 2 (power)

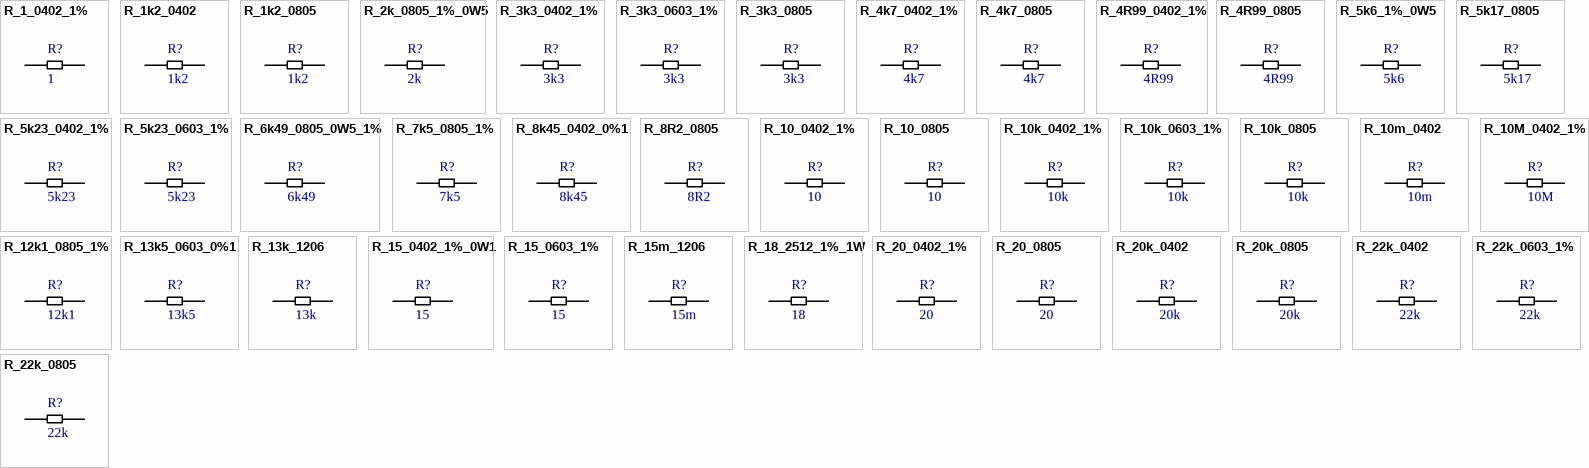
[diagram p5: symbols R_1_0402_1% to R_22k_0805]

## R_1_0402_1%
designator R?, comment 1
CRCW04021R00FKEDC
footprint R_0402
pins: 1 (power), 2 (power)

## R_1k2_0402
designator R?, comment 1k2
CRCW04021K20FKEDC
footprint R_0402
pins: 1 (power), 2 (power)

## R_1k2_0805
designator R?, comment 1k2
ERJ-6GEYJ122V
footprint R_0805
pins: 1 (power), 2 (power)

## R_2k_0805_1%_0W5
designator R?, comment 2k
AC0805FR-7W2KL
footprint R_0805
pins: 1 (power), 2 (power)

## R_3k3_0402_1%
designator R?, comment 3k3
CRCW04023K30FKED
footprint R_0402
pins: 1 (power), 2 (power)

## R_3k3_0603_1%
designator R?, comment 3k3
CRCW06033K30FKEAC
footprint R_0603
pins: 1 (power), 2 (power)

## R_3k3_0805
designator R?, comment 3k3
RCG08053K30JNEA
footprint R_0805
pins: 1 (power), 2 (power)

## R_4k7_0402_1%
designator R?, comment 4k7
CRCW04024K70FKED
footprint R_0402
pins: 1 (power), 2 (power)

## R_4k7_0805
designator R?, comment 4k7
CRCW08054K70FKEAC
footprint R_0805
pins: 1 (power), 2 (power)

## R_4R99_0402_1%
designator R?, comment 4R99
CRCW04024R99FKEDC
footprint R_0402
pins: 1 (power), 2 (power)

## R_4R99_0805
designator R?, comment 4R99
CRCW08054R99FNEA
footprint R_0805
pins: 1 (power), 2 (power)

## R_5k6_1%_0W5
designator R?, comment 5k6
ERJ-P06F5601V
footprint R_0805
pins: 1 (power), 2 (power)

## R_5k17_0805
designator R?, comment 5k17
RN732ATTD5171D25
footprint R_0805
pins: 1 (power), 2 (power)

## R_5k23_0402_1%
designator R?, comment 5k23
CRCW04025K23FKED
footprint R_0402
pins: 1 (power), 2 (power)

## R_5k23_0603_1%
designator R?, comment 5k23
CRCW06035K23FKEA
footprint R_0603
pins: 1 (power), 2 (power)

## R_6k49_0805_0W5_1%
designator R?, comment 6k49
ERJ-P06F6491V
footprint R_0805
pins: 1 (power), 2 (power)

## R_7k5_0805_1%
designator R?, comment 7k5
ERJ-P06F7501V
footprint R_0805
pins: 1 (power), 2 (power)

## R_8k45_0402_0%1
designator R?, comment 8k45
ERA-2AEB8451X
footprint R_0402
pins: 1 (power), 2 (power)

## R_8R2_0805
designator R?, comment 8R2
CRCW08058R20JNEA
footprint R_0805
pins: 1 (power), 2 (power)

## R_10_0402_1%
designator R?, comment 10
ERJ-2RKF10R0X
footprint R_0402
pins: 1 (power), 2 (power)

## R_10_0805
designator R?, comment 10
CRCW080510R0FKEAC
footprint R_0805
pins: 1 (power), 2 (power)

## R_10k_0402_1%
designator R?, comment 10k
CRCW040210K0FKEDC
footprint R_0402
pins: 1 (power), 2 (power)

## R_10k_0603_1%
designator R?, comment 10k
CRCW060310K0FKEA
footprint R_0603
pins: 1 (power), 2 (power)

## R_10k_0805
designator R?, comment 10k
CRCW080510K0FKEAC
footprint R_0805
pins: 1 (power), 2 (power)

## R_10m_0402
designator R?, comment 10m
PCS1206DR0100ET
footprint R_1206
pins: 1 (power), 2 (power)

## R_10M_0402_1%
designator R?, comment 10M
CRCW040210M0FKEDC
footprint R_0402
pins: 1 (power), 2 (power)

## R_12k1_0805_1%
designator R?, comment 12k1
ERJ-P06F1212V
footprint R_0805
pins: 1 (power), 2 (power)

## R_13k5_0603_0%1
designator R?, comment 13k5
RT0603BRD0713K5L
footprint R_0603
pins: 1 (power), 2 (power)

## R_13k_1206
designator R?, comment 13k
ERJ-8ENF1302V
footprint R_1206
pins: 1 (power), 2 (power)

## R_15_0402_1%_0W1
designator R?, comment 15
ERJ-2RKF15R0X
footprint R_0402
pins: 1 (power), 2 (power)

## R_15_0603_1%
designator R?, comment 15
CRCW060315R0FKEB
footprint R_0603
pins: 1 (power), 2 (power)

## R_15m_1206
designator R?, comment 15m
L4T12FR015FER
footprint R_1206
pins: 1 (power), 2 (power)

## R_18_2512_1%_1W
designator R?, comment 18
ERJ-1TNF18R0U
footprint R_2512
pins: 1 (power), 2 (power)

## R_20_0402_1%
designator R?, comment 20
CRCW040220R0FKEDC
footprint R_0402
pins: 1 (power), 2 (power)

## R_20_0805
designator R?, comment 20
CRCW080520R0JNEA
footprint R_0805
pins: 1 (power), 2 (power)

## R_20k_0402
designator R?, comment 20k
CRCW040220K0FKEDC
footprint R_0402
pins: 1 (power), 2 (power)

## R_20k_0805
designator R?, comment 20k
CRCW080520K0FKEAC
footprint R_0805
pins: 1 (power), 2 (power)

## R_22k_0402
designator R?, comment 22k
RG1005P-223-D-T10
footprint R_0402
pins: 1 (power), 2 (power)

## R_22k_0603_1%
designator R?, comment 22k
CRCW060322K0FKEAC
footprint R_0603
pins: 1 (power), 2 (power)

## R_22k_0805
designator R?, comment 22k
RR1220P-223-D
footprint R_0805
pins: 1 (power), 2 (power)

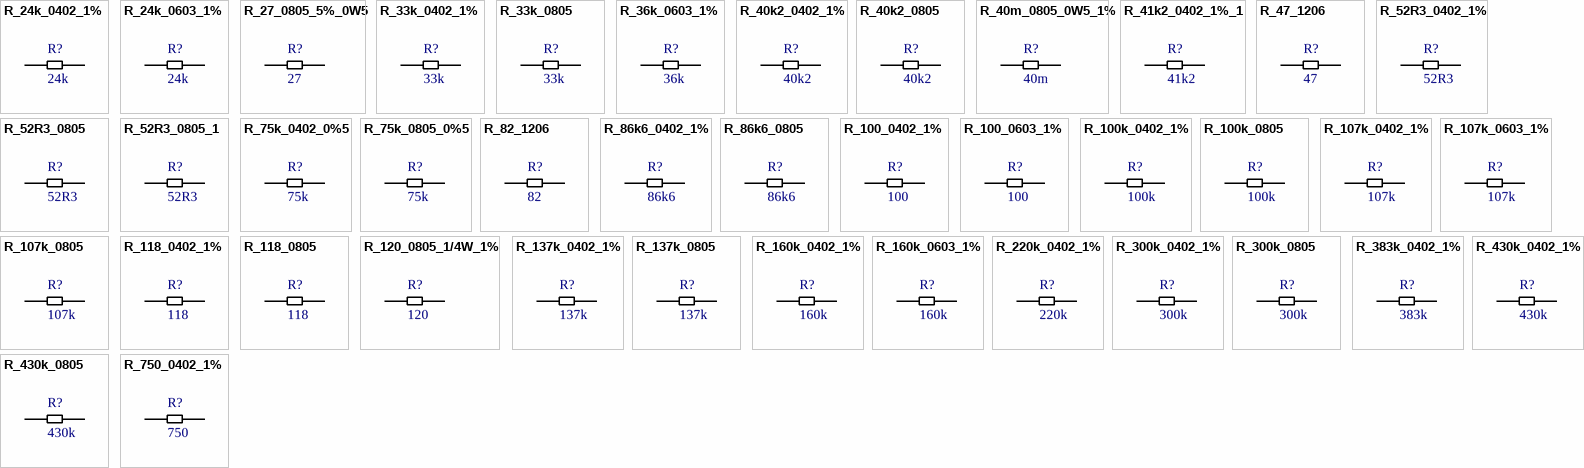
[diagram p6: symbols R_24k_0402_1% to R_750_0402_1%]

## R_24k_0402_1%
designator R?, comment 24k
ERJ-2RKF2402X
footprint R_0402
pins: 1 (power), 2 (power)

## R_24k_0603_1%
designator R?, comment 24k
CRCW060324K0FKEA
footprint R_0603
pins: 1 (power), 2 (power)

## R_27_0805_5%_0W5
designator R?, comment 27
ERJ-P06J270V
footprint R_0805
pins: 1 (power), 2 (power)

## R_33k_0402_1%
designator R?, comment 33k
CRCW040233K0FKEDC
footprint R_0402
pins: 1 (power), 2 (power)

## R_33k_0805
designator R?, comment 33k
CRCW080533K0FKEA
footprint R_0805
pins: 1 (power), 2 (power)

## R_36k_0603_1%
designator R?, comment 36k
ERJ-3EKF3602V
footprint R_0603
pins: 1 (power), 2 (power)

## R_40k2_0402_1%
designator R?, comment 40k2
CRCW040240K2FKEDC
footprint R_0402
pins: 1 (power), 2 (power)

## R_40k2_0805
designator R?, comment 40k2
RCA080540K2FKEA
footprint R_0805
pins: 1 (power), 2 (power)

## R_40m_0805_0W5_1%
designator R?, comment 40m
WSLP0805R0400FEA
footprint R_0805
pins: 1 (power), 2 (power)

## R_41k2_0402_1%_1
designator R?, comment 41k2
RC0402FR-0741K2L
footprint R_0402
pins: 1 (power), 2 (power)

## R_47_1206
designator R?, comment 47
CRCW120647R0JNEAC
footprint R_1206
pins: 1 (power), 2 (power)

## R_52R3_0402_1%
designator R?, comment 52R3
CRCW040252R3FKED
footprint R_0402
pins: 1 (power), 2 (power)

## R_52R3_0805
designator R?, comment 52R3
ERJ-6ENF52R3V
footprint R_0805
pins: 1 (power), 2 (power)

## R_52R3_0805_1
designator R?, comment 52R3
ERJ-6ENF52R3V
footprint R_0805
pins: 1 (power), 2 (power)

## R_75k_0402_0%5
designator R?, comment 75k
RR0510P-753-D
footprint R_0402
pins: 1 (power), 2 (power)

## R_75k_0805_0%5
designator R?, comment 75k
RR1220P-753-D
footprint R_0805
pins: 1 (power), 2 (power)

## R_82_1206
designator R?, comment 82
AC1206JR-0782RL
footprint R_1206
pins: 1 (power), 2 (power)

## R_86k6_0402_1%
designator R?, comment 86k6
CRCW040286K6FKED
footprint R_0402
pins: 1 (power), 2 (power)

## R_86k6_0805
designator R?, comment 86k6
CRCW080586K6FKEA
footprint R_0805
pins: 1 (power), 2 (power)

## R_100_0402_1%
designator R?, comment 100
ERJ-2RKF1000X
footprint R_0402
pins: 1 (power), 2 (power)

## R_100_0603_1%
designator R?, comment 100
CRCW0603100RFKEAC
footprint R_0603
pins: 1 (power), 2 (power)

## R_100k_0402_1%
designator R?, comment 100k
CRCW0402100KFKEDC
footprint R_0402
pins: 1 (power), 2 (power)

## R_100k_0805
designator R?, comment 100k
CRCW0805100KFKEAC
footprint R_0805
pins: 1 (power), 2 (power)

## R_107k_0402_1%
designator R?, comment 107k
CRCW0402107KFKED
footprint R_0402
pins: 1 (power), 2 (power)

## R_107k_0603_1%
designator R?, comment 107k
CRCW0603107KFKEA
footprint R_0603
pins: 1 (power), 2 (power)

## R_107k_0805
designator R?, comment 107k
CRCW0805107KFKEA
footprint R_0805
pins: 1 (power), 2 (power)

## R_118_0402_1%
designator R?, comment 118
CRCW0402118RFKED
footprint R_0402
pins: 1 (power), 2 (power)

## R_118_0805
designator R?, comment 118
CRCW0805118RFKEA
footprint R_0805
pins: 1 (power), 2 (power)

## R_120_0805_1/4W_1%
designator R?, comment 120
RK73H2ATTD1200F
footprint R_0805
pins: 1 (power), 2 (power)

## R_137k_0402_1%
designator R?, comment 137k
CRCW0402137KFKED
footprint R_0402
pins: 1 (power), 2 (power)

## R_137k_0805
designator R?, comment 137k
CRCW0805137KFKEA
footprint R_0805
pins: 1 (power), 2 (power)

## R_160k_0402_1%
designator R?, comment 160k
CRCW0402160KFKED
footprint R_0402
pins: 1 (power), 2 (power)

## R_160k_0603_1%
designator R?, comment 160k
CRCW0603160KFKEA
footprint R_0603
pins: 1 (power), 2 (power)

## R_220k_0402_1%
designator R?, comment 220k
CRCW0402220KFKEDC
footprint R_0402
pins: 1 (power), 2 (power)

## R_300k_0402_1%
designator R?, comment 300k
CRCW0402300KFKEDC
footprint R_0402
pins: 1 (power), 2 (power)

## R_300k_0805
designator R?, comment 300k
CRCW0805300KJNEA
footprint R_0805
pins: 1 (power), 2 (power)

## R_383k_0402_1%
designator R?, comment 383k
CRCW0402383KFKED
footprint R_0402
pins: 1 (power), 2 (power)

## R_430k_0402_1%
designator R?, comment 430k
CRCW0402430KFKED
footprint R_0402
pins: 1 (power), 2 (power)

## R_430k_0805
designator R?, comment 430k
CRCW0805430KFKEA
footprint R_0805
pins: 1 (power), 2 (power)

## R_750_0402_1%
designator R?, comment 750
CRCW0402750RFKEDC
footprint R_0805
pins: 1 (power), 2 (power)

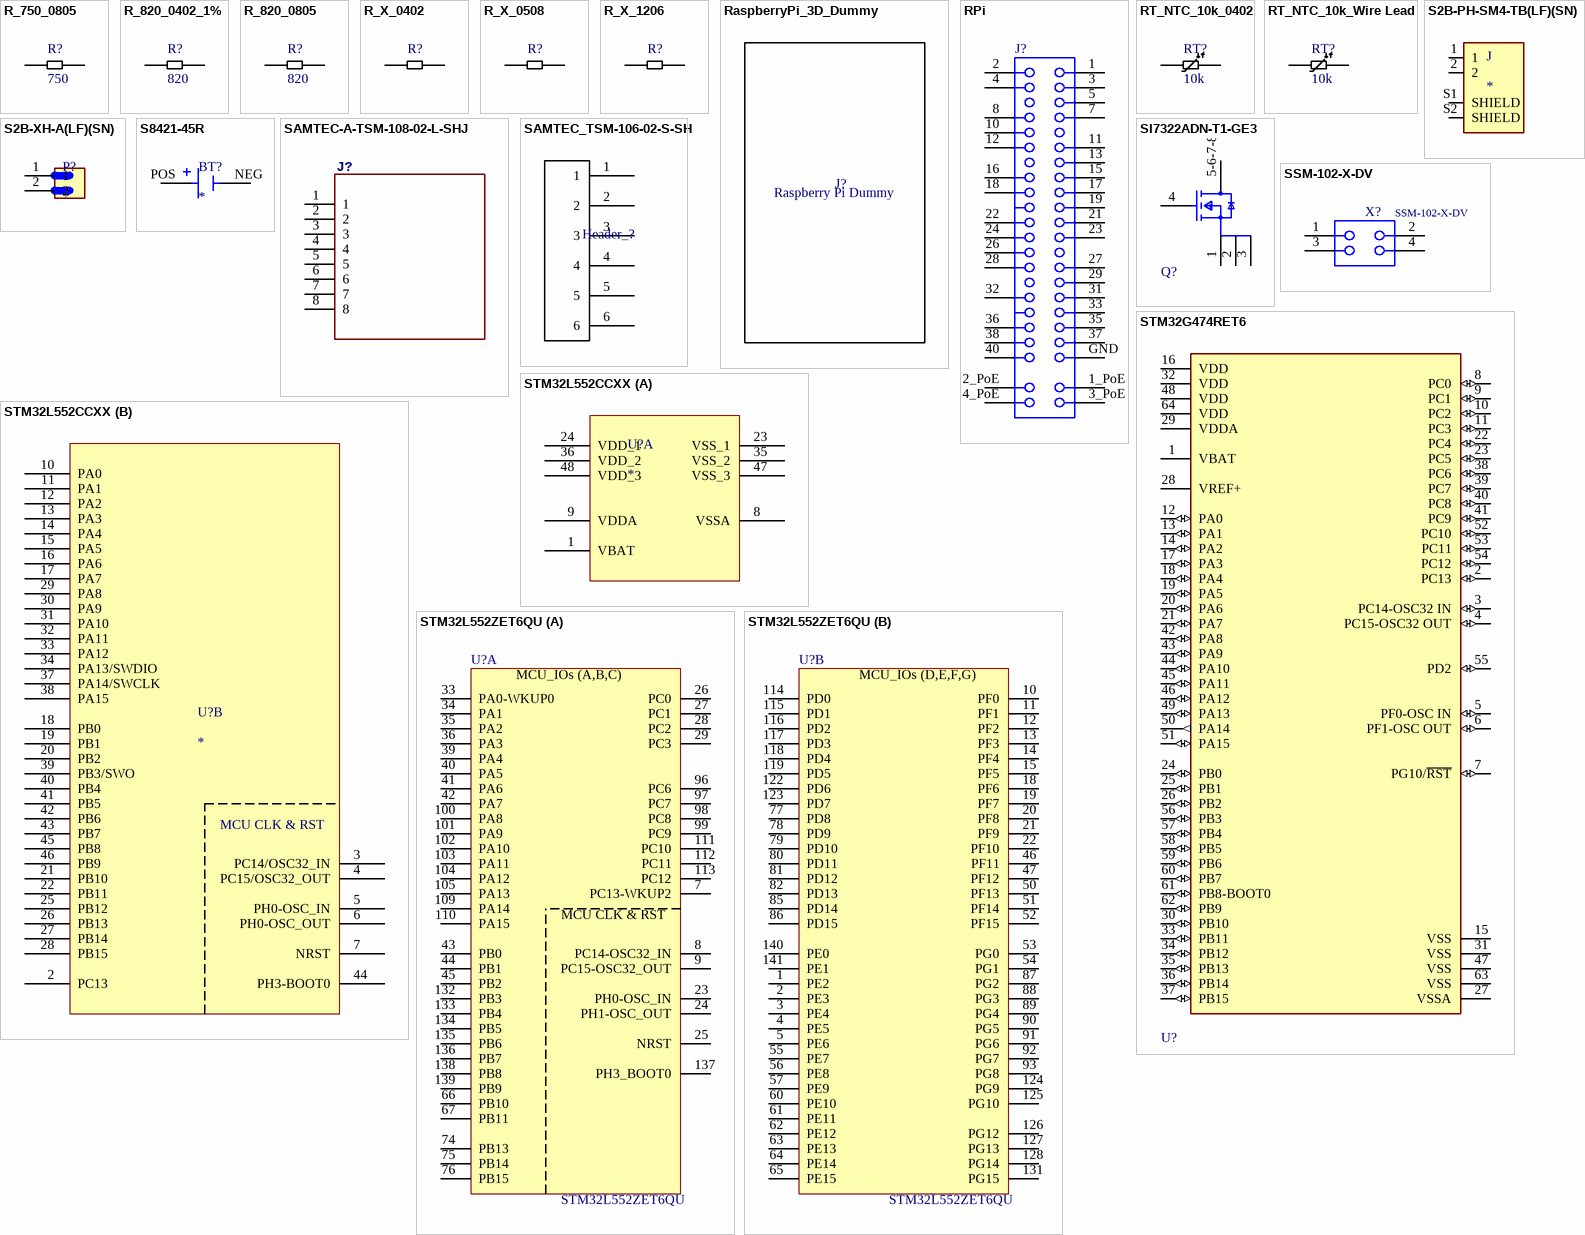
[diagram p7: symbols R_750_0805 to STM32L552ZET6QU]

## R_750_0805
designator R?, comment 750
ERJ-6GEYJ751V
footprint R_0805
pins: 1 (power), 2 (power)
